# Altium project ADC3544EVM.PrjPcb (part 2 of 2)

## Sheet ADC Inputs.SchDoc: ADC Inputs
size 431 x 279 mm; Date: Not shown in title block; ApprovedBy: Not shown in title block; CheckedBy: Not shown in title block; Author: Not shown in title block; CompanyName: Not shown in title block; Engineer: Not shown in title block; Organization: Not shown in title block; Address1: Not shown in title block; Address2: Not shown in title block; Address3: Not shown in title block; Address4: Not shown in title block; DocumentNumber: 1; Revision: Use project parameter SCH_Rev; SheetNumber: 9; SheetTotal: 15; PageSetup: Record=PageOptions¦CenterHorizontal=True¦CenterVertical=True¦PrintScale=1.00¦XCorrection=1.00¦YCorrection=1.00¦PrintKind=0¦BorderSize=5000000¦LeftOffset=0¦BottomOffset=0¦Orientation=2¦PaperLength=1000¦PaperWidth=1000¦Scale=100¦PaperSource=15¦PrintQuality=600¦MediaType=1¦DitherType=10¦PaperKind=Letter¦PrintScaleMode=1
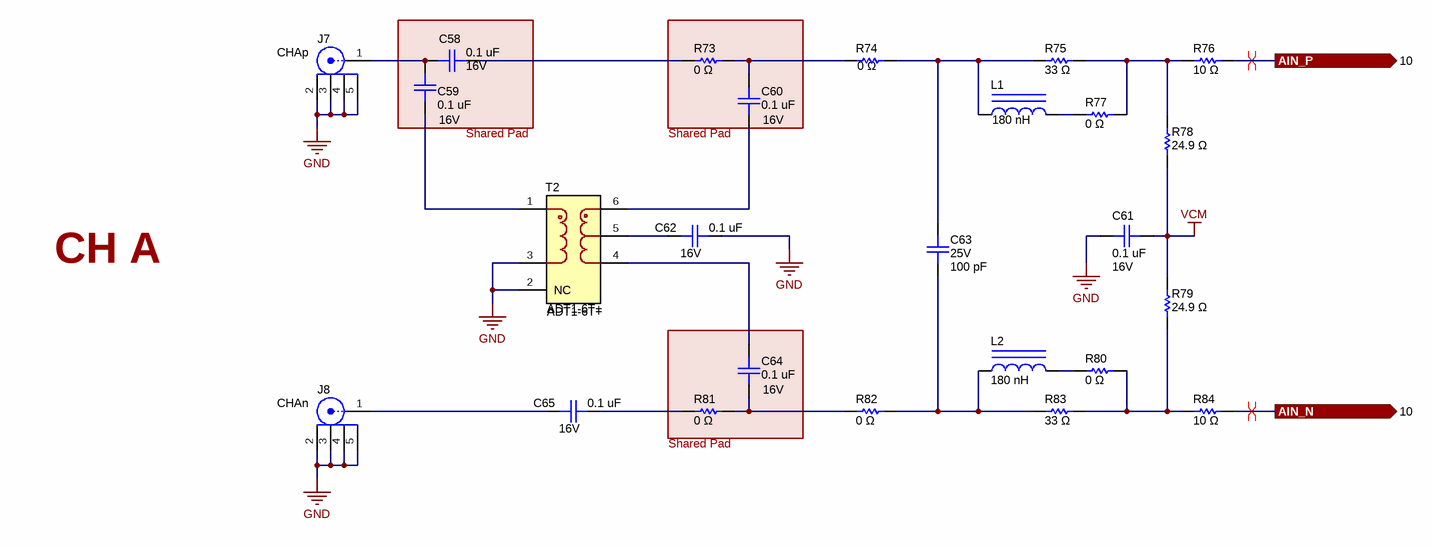
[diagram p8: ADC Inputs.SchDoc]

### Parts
(Parts that share a designator on the sheet are numbered #1, #2 ... from top to bottom, then left to right.)
?#4  Shared Pad  (graphical)
?#5  Shared Pad  (graphical)
?#6  Shared Pad  (graphical)
C58  value 0.1 uF  Voltage - Rated: 16V  [0201_cap]  (hidden comment: GRM033Z71C104ME14D)
C59  value 0.1 uF  Voltage - Rated: 16V  [0201_cap]  (hidden comment: GRM033Z71C104ME14D)
C60  value 0.1 uF  Voltage - Rated: 16V  [0201_cap]  (hidden comment: GRM033Z71C104ME14D)
C61  value 0.1 uF  Voltage - Rated: 16V  [0201_cap]  (hidden comment: GRM033Z71C104ME14D)
C62  value 0.1 uF  Voltage - Rated: 16V  [0201_cap]  (hidden comment: GRM033Z71C104ME14D)
C63  value 100 pF  Voltage - Rated: 25V  [0201_cap]  (hidden comment: CGA1A2X7R1E101M030BA)
C64  value 0.1 uF  Voltage - Rated: 16V  [0201_cap]  (hidden comment: GRM033Z71C104ME14D)
C65  value 0.1 uF  Voltage - Rated: 16V  [0201_cap]  (hidden comment: GRM033Z71C104ME14D)
J7  Text1: CHAp  [FP-132134-15_CONN_SMA_JACK-MFG]  (hidden comment: 132134-15)
J8  Text1: CHAn  [FP-132134-15_CONN_SMA_JACK-MFG]  (hidden comment: 132134-15)
L1  180 nH  [IND_LQG15H]
L2  180 nH  [IND_LQG15H]
R73  value 0 Ω  [0201]  (hidden comment: ERJ-1GN0R00C)
R74  value 0 Ω  [0201]  (hidden comment: ERJ-1GN0R00C)
R75  value 33 Ω  [0201]  (hidden comment: ERJ-1GNF33R0C)
R76  value 10 Ω  [0201]  (hidden comment: ERJ-1GNF10R0C)
R77  value 0 Ω  [0201]  (hidden comment: ERJ-1GN0R00C)
R78  value 24.9 Ω  [0201]  (hidden comment: ERJ-1GNF24R9C)
R79  value 24.9 Ω  [0201]  (hidden comment: ERJ-1GNF24R9C)
R80  value 0 Ω  [0201]  (hidden comment: ERJ-1GN0R00C)
R81  value 0 Ω  [0201]  (hidden comment: ERJ-1GN0R00C)
R82  value 0 Ω  [0201]  (hidden comment: ERJ-1GN0R00C)
R83  value 33 Ω  [0201]  (hidden comment: ERJ-1GNF33R0C)
R84  value 10 Ω  [0201]  (hidden comment: ERJ-1GNF10R0C)
T2  ADT1-6T+  [CD637]

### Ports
AIN_N (out, see 10), AIN_P (out, see 10)

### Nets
GND: C61.1 C62.2 J7.2 J7.3 J7.4 J7.5 J8.2 J8.3 J8.4 J8.5 T2.2(NC) T2.3
VCM: C61.2 R78.1 R79.2
AIN_N: R84.2 ; port AIN_N
AIN_P: R76.2 ; port AIN_P
NetC58_1: C58.1 C59.1 J7.1
NetC58_2: C58.2 R73.1
NetC59_2: C59.2 T2.1
NetC60_1: C60.1 T2.6
NetC60_2: C60.2 R73.2 R74.1
NetC62_1: C62.1 T2.5
NetC63_1: C63.1 L2.1 R82.2 R83.1
NetC63_2: C63.2 L1.1 R74.2 R75.1
NetC64_1: C64.1 R81.2 R82.1
NetC64_2: C64.2 T2.4
NetC65_1: C65.1 J8.1
NetC65_2: C65.2 R81.1
NetL1_2: L1.2 R77.1
NetL2_2: L2.2 R80.1
NetR75_2: R75.2 R76.1 R77.2 R78.2
NetR79_1: R79.1 R80.2 R83.2 R84.1

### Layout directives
differential pair: AIN_N, AIN_P

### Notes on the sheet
- CH A

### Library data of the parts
?#4-?#6 = Swizzle: Schematic notation to show that the pads of two components should be overlapped
C58-C62 C64 C65 = capcc09270: CAP CER 0.1UF 16V X7R 0201; Manufacturer: Murata Electronics; CompType: Capacitor Ceramic; Tolerance: ±20%; SizeX_mm: 0.6; SizeY_mm: 0.3; SizeZ_mm: 0.33
C63 = capcc06388: CAP CER 100PF 25V X7R 0201; Manufacturer: TDK Corporation; CompType: Capacitor Ceramic; Tolerance: ±20%; SizeX_mm: 0.6; SizeY_mm: 0.3; SizeZ_mm: 0.33
J7 J8 = 132134-15: SMA Connector Jack, Female Socket 50Ohm Surface Mount, Through Hole Solder; Manufacturer: Amphenol RF; UniqueID: cmp00028; CompType: RF Connector
L1 L2 = LQG15HSR18J02D: Inductor, Multilayer, Air Core, 180 nH, 0.14 A, 3.38 ohm, SMD; Manufacturer: MuRata; Isat: 0.14A @ % inductance drop; Irms: 0.14A @ C rise; Green_Lifecycle: Active; SizeAreaWB_mm2: 3; DCR_ohm: 3.38; Green_REACh: Passed; Value: 180nH; Imax_A: 140mA; SizeZ_mm: 0.55; SizeX_mm: 1; SizeY_mm: 0.5; Value2: 0.14A; AEC Category: Q200
R73 R74 R77 R80-R82 = RSMD020101699: RES SMD 0 OHM JUMPER 1/20W 0201; Manufacturer: Panasonic Electronic Components; CompType: Resistor SMD; Power (Watts): 0.05W, 1/20W
R75 R83 = RSMD020100013: RES SMD 33 OHM 1% 1/20W 0201; Manufacturer: Panasonic Electronic Components; CompType: Resistor SMD; Power (Watts): 0.05W, 1/20W; Temperature Coefficient: ±200ppm/°C
R76 R84 = RSMD020100179: RES SMD 10 OHM 1% 1/20W 0201; Manufacturer: Panasonic Electronic Components; CompType: Resistor SMD; Power (Watts): 0.05W, 1/20W; Temperature Coefficient: ±200ppm/°C
R78 R79 = RSMD020100010: RES SMD 24.9 OHM 1% 1/20W 0201; Manufacturer: Panasonic Electronic Components; CompType: Resistor SMD; Power (Watts): 0.05W, 1/20W; Temperature Coefficient: ±200ppm/°C
T2 = ADT1-6T+: Transformer 50Ω/0.03 to 125 MHz; Manufacturer: Mini-Circuits; Rsec1_ohm: 50; Symbol Name: SYM-ADT1-6T+; Ns1toNp: 1:1; SizeZ_mm: .206inch; AEC Qualified: No

## Sheet DUT IO.SchDoc: ADC IO
size 431 x 279 mm; Date: Not shown in title block; ApprovedBy: Not shown in title block; CheckedBy: Not shown in title block; Author: Not shown in title block; CompanyName: Not shown in title block; Engineer: Not shown in title block; Organization: Not shown in title block; Address1: Not shown in title block; Address2: Not shown in title block; Address3: Not shown in title block; Address4: Not shown in title block; DocumentNumber: 1; Revision: Use project parameter SCH_Rev; SheetNumber: 10; SheetTotal: 15; PageSetup: Record=PageOptions¦CenterHorizontal=True¦CenterVertical=True¦PrintScale=1.00¦XCorrection=1.00¦YCorrection=1.00¦PrintKind=0¦BorderSize=5000000¦LeftOffset=0¦BottomOffset=0¦Orientation=2¦PaperLength=1000¦PaperWidth=1000¦Scale=100¦PaperSource=15¦PrintQuality=600¦MediaType=1¦DitherType=10¦PaperKind=Letter¦PrintScaleMode=1
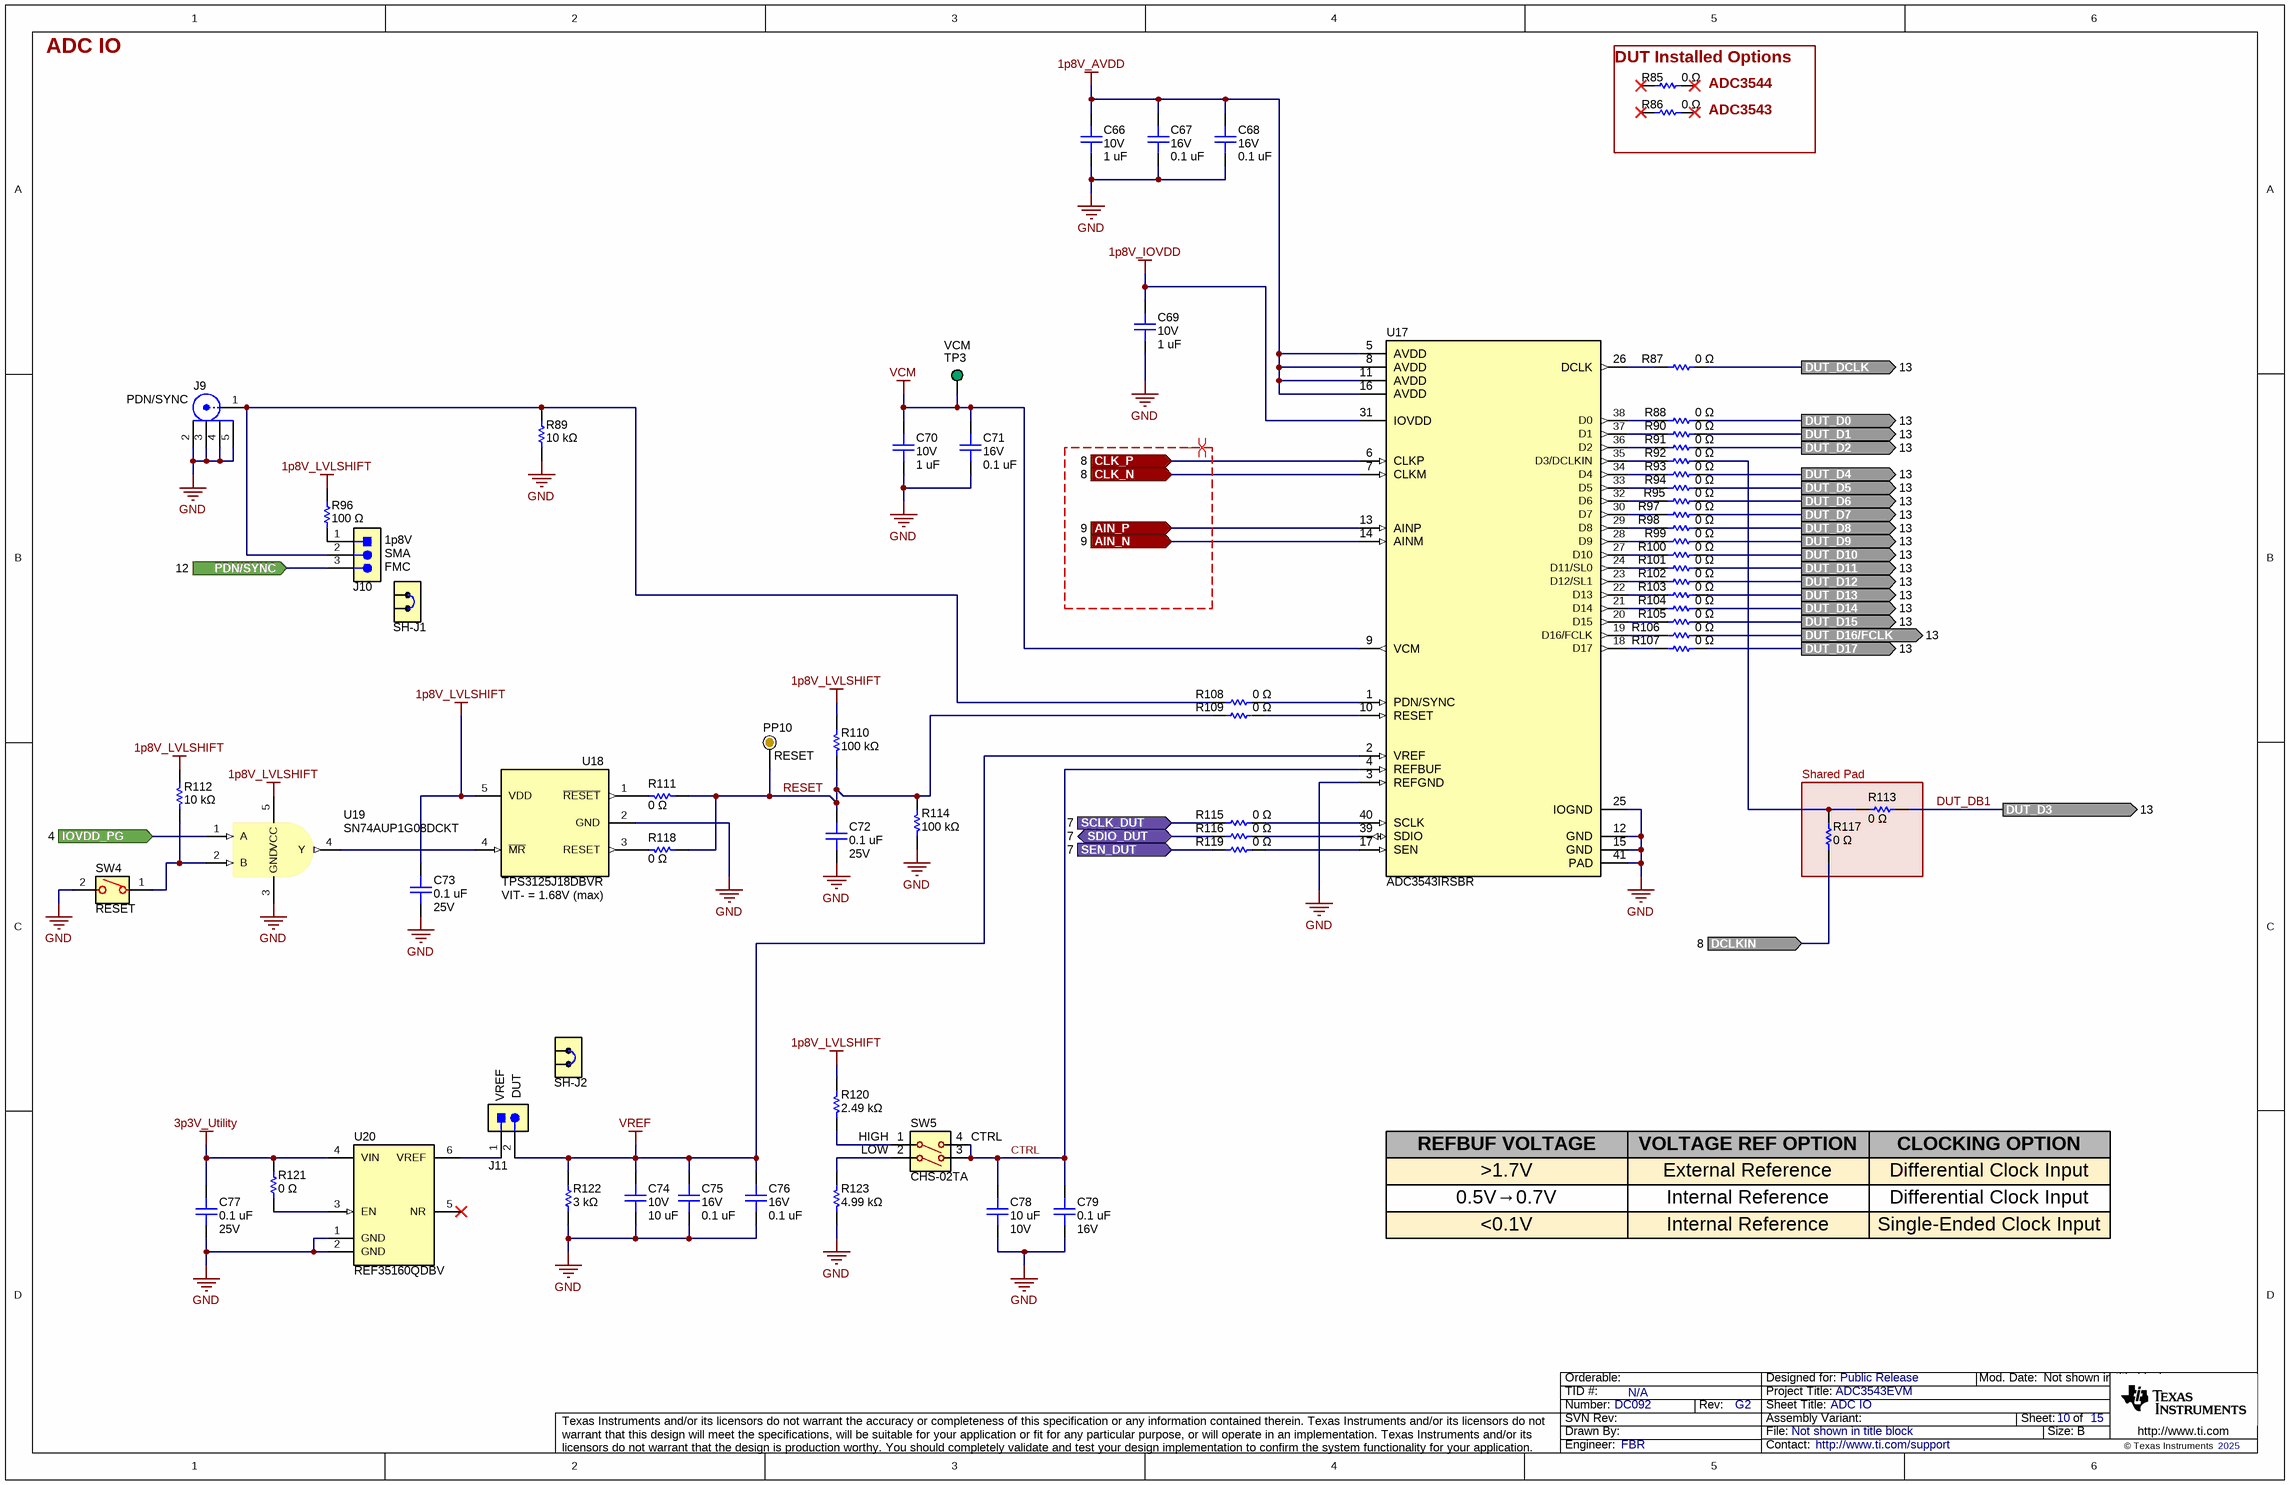
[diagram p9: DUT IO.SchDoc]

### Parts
(Parts that share a designator on the sheet are numbered #1, #2 ... from top to bottom, then left to right.)
?#7  Shared Pad  (graphical)
C66  value 1 uF  Voltage - Rated: 10V  [0201_cap]  (hidden comment: GRM033R61A105ME44D)
C67  value 0.1 uF  Voltage - Rated: 16V  [0201_cap]  (hidden comment: GRM033Z71C104ME14D)
C68  value 0.1 uF  Voltage - Rated: 16V  [0201_cap]  (hidden comment: GRM033Z71C104ME14D)
C69  value 1 uF  Voltage - Rated: 10V  [0201_cap]  (hidden comment: GRM033R61A105ME44D)
C70  value 1 uF  Voltage - Rated: 10V  [0201_cap]  (hidden comment: GRM033R61A105ME44D)
C71  value 0.1 uF  Voltage - Rated: 16V  [0201_cap]  (hidden comment: GRM033Z71C104ME14D)
C72  value 0.1 uF  Voltage - Rated: 25V  [0402L_cap]  (hidden comment: GRT155R71E104KE01J)
C73  value 0.1 uF  Voltage - Rated: 25V  [0402L_cap]  (hidden comment: GRT155R71E104KE01J)
C74  value 10 uF  Voltage - Rated: 10V  [0402L_cap]  (hidden comment: 0402ZD106MAT2A)
C75  value 0.1 uF  Voltage - Rated: 16V  [0201_cap]  (hidden comment: GRM033Z71C104ME14D)
C76  value 0.1 uF  Voltage - Rated: 16V  [0201_cap]  (hidden comment: GRM033Z71C104ME14D)
C77  value 0.1 uF  Voltage - Rated: 25V  [0402L_cap]  (hidden comment: GRT155R71E104KE01J)
C78  value 10 uF  Voltage - Rated: 10V  [0402L_cap]  (hidden comment: 0402ZD106MAT2A)
C79  value 0.1 uF  Voltage - Rated: 16V  [0201_cap]  (hidden comment: GRM033Z71C104ME14D)
J9  Text1: PDN/SYNC  [FP-132134-15_CONN_SMA_JACK-MFG]  (hidden comment: 132134-15)
J10  Text3: FMC  Text2: SMA  Text1: 1p8V  [PBC03SAAN]  (hidden comment: TSW-103-14-L-S)
J11  Text2: DUT  Text1: VREF  [HDR_2x1_TH_VT_50mil]  (hidden comment: GRPB021VWVN-RC)
PP10  Text1: RESET  [ProbePoint_TH_40mil]  (hidden comment: Probe Point)  (no BOM)
R85  value 0 Ω  [0805L]  (hidden comment: ERJ-6GEY0R00V)
R86  value 0 Ω  [0805L]  (hidden comment: ERJ-6GEY0R00V)
R87  value 0 Ω  [0201]  (hidden comment: ERJ-1GN0R00C)
R88  value 0 Ω  [0201]  (hidden comment: ERJ-1GN0R00C)
R89  value 10 kΩ  [0402L]  (hidden comment: ERA-2AEB103X)
R90  value 0 Ω  [0201]  (hidden comment: ERJ-1GN0R00C)
R91  value 0 Ω  [0201]  (hidden comment: ERJ-1GN0R00C)
R92  value 0 Ω  [0201]  (hidden comment: ERJ-1GN0R00C)
R93  value 0 Ω  [0201]  (hidden comment: ERJ-1GN0R00C)
R94  value 0 Ω  [0201]  (hidden comment: ERJ-1GN0R00C)
R95  value 0 Ω  [0201]  (hidden comment: ERJ-1GN0R00C)
R96  value 100 Ω  [0402L]  (hidden comment: ERJ-2GEJ101X)
R97  value 0 Ω  [0201]  (hidden comment: ERJ-1GN0R00C)
R98  value 0 Ω  [0201]  (hidden comment: ERJ-1GN0R00C)
R99  value 0 Ω  [0201]  (hidden comment: ERJ-1GN0R00C)
R100  value 0 Ω  [0201]  (hidden comment: ERJ-1GN0R00C)
R101  value 0 Ω  [0201]  (hidden comment: ERJ-1GN0R00C)
R102  value 0 Ω  [0201]  (hidden comment: ERJ-1GN0R00C)
R103  value 0 Ω  [0201]  (hidden comment: ERJ-1GN0R00C)
R104  value 0 Ω  [0201]  (hidden comment: ERJ-1GN0R00C)
R105  value 0 Ω  [0201]  (hidden comment: ERJ-1GN0R00C)
R106  value 0 Ω  [0201]  (hidden comment: ERJ-1GN0R00C)
R107  value 0 Ω  [0201]  (hidden comment: ERJ-1GN0R00C)
R108  value 0 Ω  [0201]  (hidden comment: ERJ-1GN0R00C)
R109  value 0 Ω  [0201]  (hidden comment: ERJ-1GN0R00C)
R110  value 100 kΩ  [0402L]  (hidden comment: ERJ-2GEJ104X)
R111  value 0 Ω  [0402L]  (hidden comment: ERJ-U020R00X)
R112  value 10 kΩ  [0402L]  (hidden comment: ERA-2AEB103X)
R113  value 0 Ω  [0201]  (hidden comment: ERJ-1GN0R00C)
R114  value 100 kΩ  [0402L]  (hidden comment: ERJ-2GEJ104X)
R115  value 0 Ω  [0201]  (hidden comment: ERJ-1GN0R00C)
R116  value 0 Ω  [0201]  (hidden comment: ERJ-1GN0R00C)
R117  value 0 Ω  [0201]  (hidden comment: ERJ-1GN0R00C)
R118  value 0 Ω  [0402L]  (hidden comment: ERJ-U020R00X)
R119  value 0 Ω  [0201]  (hidden comment: ERJ-1GN0R00C)
R120  value 2.49 kΩ  [0201]  (hidden comment: ERJ-1GNF2491C)
R121  value 0 Ω  [0201]  (hidden comment: ERJ-1GN0R00C)
R122  value 3 kΩ  [0201]  (hidden comment: ERJ-1GNF3001C)
R123  value 4.99 kΩ  [0201]  (hidden comment: ERJ-1GNF4991C)
SH-J1  SPC02SYAN  [SPC02SYAN]  (value not drawn)
SH-J2  HMSC-G  [HMSC-G]  (value not drawn)
SW4  Text1: RESET  [FSMSM]  (hidden comment: FSMSM)
SW5  CHS-02TA  Text4: CTRL  Text2: LOW  Text1: HIGH  [CHS-02TA]
TP3  Text1: VCM  [KEYSTONE5116]  (hidden comment: 5116)
U17  ADC3543IRSBR  [RSB0040E]
U18  TPS3125J18DBVR  Text1: VIT- = 1.68V (max)  [DBV0005A]
U19  SN74AUP1G08DCKT  [DCK0005A]
U20  REF35160QDBV  [DBV0006A]

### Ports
AIN_N (in, see 9), AIN_P (in, see 9), CLK_N (in, see 8), CLK_P (in, see 8), DCLKIN (in, see 8), DUT_D0 (out, see 13), DUT_D1 (out, see 13), DUT_D2 (out, see 13), DUT_D3 (out, see 13), DUT_D4 (out, see 13), DUT_D5 (out, see 13), DUT_D6 (out, see 13), DUT_D7 (out, see 13), DUT_D8 (out, see 13), DUT_D9 (out, see 13), DUT_D10 (out, see 13), DUT_D11 (out, see 13), DUT_D12 (out, see 13), DUT_D13 (out, see 13), DUT_D14 (out, see 13), DUT_D15 (out, see 13), DUT_D16/FCLK (out, see 13), DUT_D17 (out, see 13), DUT_DCLK (out, see 13), IOVDD_PG (in, see 4), PDN/SYNC (in, see 12), SCLK_DUT (in, see 7), SDIO_DUT (bidir, see 7), SEN_DUT (in, see 7)

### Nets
1p8V_AVDD: C66.2 C67.2 C68.2 U17.5(AVDD) U17.8(AVDD) U17.11(AVDD) U17.16(AVDD)
1p8V_IOVDD: C69.2 U17.31(IOVDD)
1p8V_LVLSHIFT: C73.2 R96.2 R110.2 R112.1 R120.2 U18.5(VDD) U19.5(VCC)
3p3V_Utility: C77.2 R121.2 U20.4(VIN)
GND: C66.1 C67.1 C68.1 C69.1 C70.1 C71.1 C72.1 C73.1 C74.1 C75.1 C76.1 C77.1 C78.1 C79.1 J9.2 J9.3 J9.4 J9.5 R89.1 R114.1 R122.1 R123.1 SW4.2 U17.3(REFGND) U17.12(GND) U17.15(GND) U17.25(IOGND) U17.41(PAD) U18.2(GND) U19.3(GND) U20.1(GND) U20.2(GND)
VCM: C70.2 C71.2 TP3.1 U17.9(VCM)
VREF: C74.2 C75.2 C76.2 J11.2 R122.2 U17.2(VREF)
AIN_N: U17.14(AINM) ; port AIN_N
AIN_P: U17.13(AINP) ; port AIN_P
CLK_N: U17.7(CLKM) ; port CLK_N
CLK_P: U17.6(CLKP) ; port CLK_P
CTRL: C78.2 C79.2 SW5.3(OFF) SW5.4(OFF) U17.4(REFBUF)
DCLKIN: R117.1 ; port DCLKIN
DUT_D0: R88.2 ; port DUT_D0
DUT_D1: R90.2 ; port DUT_D1
DUT_D2: R91.2 ; port DUT_D2
DUT_D4: R93.2 ; port DUT_D4
DUT_D5: R94.2 ; port DUT_D5
DUT_D6: R95.2 ; port DUT_D6
DUT_D7: R97.2 ; port DUT_D7
DUT_D8: R98.2 ; port DUT_D8
DUT_D9: R99.2 ; port DUT_D9
DUT_D10: R100.2 ; port DUT_D10
DUT_D11: R101.2 ; port DUT_D11
DUT_D12: R102.2 ; port DUT_D12
DUT_D13: R103.2 ; port DUT_D13
DUT_D14: R104.2 ; port DUT_D14
DUT_D15: R105.2 ; port DUT_D15
DUT_D16/FCLK: R106.2 ; port DUT_D16/FCLK
DUT_D17: R107.2 ; port DUT_D17
DUT_DB1: R113.1 ; port DUT_D3
DUT_DCLK: R87.2 ; port DUT_DCLK
IOVDD_PG: U19.1(A) ; port IOVDD_PG
PDN/SYNC: J10.3 ; port PDN/SYNC
RESET: C72.2 PP10.1 R109.1 R110.1 R111.1 R114.2 R118.1
SCLK_DUT: R115.1 ; port SCLK_DUT
SDIO_DUT: R116.1 ; port SDIO_DUT
SEN_DUT: R119.1 ; port SEN_DUT
NetJ9_1: J9.1 J10.2 R89.2 R108.1
NetJ10_1: J10.1 R96.1
NetJ11_1: J11.1 U20.6(VREF)
NetR87_1: R87.1 U17.26(DCLK)
NetR88_1: R88.1 U17.38(D0)
NetR90_1: R90.1 U17.37(D1)
NetR91_1: R91.1 U17.36(D2)
NetR92_1: R92.1 U17.35(D3/DCLKIN)
NetR92_2: R92.2 R113.2 R117.2
NetR93_1: R93.1 U17.34(D4)
NetR94_1: R94.1 U17.33(D5)
NetR95_1: R95.1 U17.32(D6)
NetR97_1: R97.1 U17.30(D7)
NetR98_1: R98.1 U17.29(D8)
NetR99_1: R99.1 U17.28(D9)
NetR100_1: R100.1 U17.27(D10)
NetR101_1: R101.1 U17.24(D11/SL0)
NetR102_1: R102.1 U17.23(D12/SL1)
NetR103_1: R103.1 U17.22(D13)
NetR104_1: R104.1 U17.21(D14)
NetR105_1: R105.1 U17.20(D15)
NetR106_1: R106.1 U17.19(D16/FCLK)
NetR107_1: R107.1 U17.18(D17)
NetR108_2: R108.2 U17.1(PDN/SYNC)
NetR109_2: R109.2 U17.10(RESET)
NetR111_2: R111.2 U18.1(~{RESET})
NetR112_2: R112.2 SW4.1 U19.2(B)
NetR115_2: R115.2 U17.40(SCLK)
NetR116_2: R116.2 U17.39(SDIO)
NetR118_2: R118.2 U18.3(RESET)
NetR119_2: R119.2 U17.17(SEN)
NetR120_1: R120.1 SW5.1(ON)
NetR121_1: R121.1 U20.3(EN)
NetR123_2: R123.2 SW5.2(ON)
NetU18_4: U18.4(~{MR}) U19.4(Y)

Not connected (* = marked no-connect by the designer): R85 1* 2*; R86 1* 2*; U20 5(NR)*

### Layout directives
differential pair; net class DiffPairIN: (no net found under the mark)

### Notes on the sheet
- ADC3544
- DUT Installed Options
- ADC3543
- REFBUF VOLTAGE
- VOLTAGE REF OPTION
- CLOCKING OPTION
- >1.7V
- 0.5V→0.7V
- <0.1V
- External Reference
- Internal Reference
- Differential Clock Input
- Single-Ended Clock Input

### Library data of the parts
?#7 = Swizzle: as ?#4-?#6 on sheet ADC Inputs
C66 C69 C70 = capcc09264: CAP CER 1UF 10V X5R 0201; Manufacturer: Murata Electronics; CompType: Capacitor Ceramic; Tolerance: ±20%; SizeX_mm: 0.6; SizeY_mm: 0.3; SizeZ_mm: 0.33
C67 C68 C71 C75 C76 C79 = capcc09270: as C58-C62 on sheet ADC Inputs
C72 C73 C77 = capcc09401: CAP CER 0.1UF 25V X7R 0402; Manufacturer: Murata; CompType: Capacitor Ceramic; Tolerance: ±10%; SizeX_mm: 1; SizeY_mm: 0.5; SizeZ_mm: 0.7
C74 C78 = capcc09406: CAP CER 10UF 10V X5R 0402; Manufacturer: KYOCERA AVX; CompType: Capacitor Ceramic; Tolerance: ±20%; SizeX_mm: 1; SizeY_mm: 0.5; SizeZ_mm: 0.7
J9 = 132134-15: as J7 on sheet ADC Inputs
J10 = TSW-103-14-L-S: Header, 100mil, 3x1, Gold, TH; Manufacturer: Samtec; Alt Manufacturer: Sullins Connector Solutions; UniqueID: cmp00015; Pitch (mm): 2.54
J11 = cmp00298: Header, 50mil, 2x1, Gold, TH; Manufacturer: Sullins Connector Solutions; Pitch (mm): 1.27
PP10 = Probe Point: Probe Point that can be used in lue of a test point; UniqueID: cmp00025
R85 R86 = RSMD080510615: RES SMD 0 OHM JUMPER 1/8W 0805; Manufacturer: Panasonic Electronic Components; CompType: Resistor SMD; Power (Watts): 0.125W, 1/8W; SizeX_mm: 2; SizeY_mm: 1.25; SizeZ_mm: 0.7
R87 R88 R90-R95 R97-R109 R113 R115-R117 R119 R121 = RSMD020101699: as R73 on sheet ADC Inputs
R89 R112 = RSMD040200315: RES SMD 10K OHM 0.1% 1/16W 0402; Manufacturer: Panasonic Electronic Components; CompType: Resistor SMD; Power (Watts): 0.063W, 1/16W; Temperature Coefficient: ±25ppm/°C; SizeX_mm: 1; SizeY_mm: 0.5; SizeZ_mm: 0.4
R96 = RSMD040200370: RES SMD 100 OHM 5% 1/10W 0402; Manufacturer: Panasonic Electronic Components; CompType: Resistor SMD; Power (Watts): 0.1W, 1/10W; Temperature Coefficient: ±200ppm/°C; SizeX_mm: 1; SizeY_mm: 0.5; SizeZ_mm: 0.4
R110 R114 = RSMD040200354: RES SMD 100K OHM 5% 1/10W 0402; Manufacturer: Panasonic Electronic Components; CompType: Resistor SMD; Power (Watts): 0.1W, 1/10W; Temperature Coefficient: ±200ppm/°C; SizeX_mm: 1; SizeY_mm: 0.5; SizeZ_mm: 0.4
R111 R118 = RSMD040200004: RES 0 OHM JUMPER 0402 SMD; Manufacturer: Panasonic Electronic Components; CompType: Resistor SMD; Power (Watts): 0.1W, 1/10W; Temperature Coefficient: -100/ +600ppm/°C; SizeX_mm: 1; SizeY_mm: 0.5; SizeZ_mm: 0.4
R120 = RSMD020100692: RES SMD 2.49K OHM 1% 1/20W 0201; Manufacturer: Panasonic Electronic Components; CompType: Resistor SMD; Power (Watts): 0.05W, 1/20W; Temperature Coefficient: ±200ppm/°C
R122 = RSMD020100769: RES SMD 3K OHM 1% 1/20W 0201; Manufacturer: Panasonic Electronic Components; CompType: Resistor SMD; Power (Watts): 0.05W, 1/20W; Temperature Coefficient: ±200ppm/°C
R123 = RSMD020100641: RES SMD 4.99K OHM 1% 1/20W 0201; Manufacturer: Panasonic Electronic Components; CompType: Resistor SMD; Power (Watts): 0.05W, 1/20W; Temperature Coefficient: ±200ppm/°C
SH-J1 = cmp00299: 2 (1 x 2) Position Shunt Connector Black Closed Top 0.050" (1.27mm) Gold; Manufacturer: Adam Tech; PartNumber: HMSC-G; Value: 1x2; Note: You can "mate" this to a header by matching the designator.  i.e. use SH-J3 for header J3; Pitch (mm): 1.27
SH-J2 = HMSC-G: 2 (1 x 2) Position Shunt Connector Black Closed Top 0.050" (1.27mm) Gold; Manufacturer: Adam Tech; Value: 1x2; Key: SPC02SYAN; Note: You can "mate" this to a header by matching the designator.  i.e. use SH-J3 for header J3; Pitch (mm): 1.27
SW4 = cmp00234: SWITCH TACTILE SPST-NO 0.05A 24V; Manufacturer: TE Connectivity; CompType: Push Button
SW5 = CHS-02TA: SWITCH SLIDE DIP SPST 0.1A 6V; Manufacturer: Nidec Components Corporation; CompType: Swtich
TP3 = cmp00057: Test Point, Miniature, Green, TH; Manufacturer: Keystone
U17 = ADC3543IRSB: Single-channel, 14-bit, 65-MSPS, low-noise, ultra-low-power and low-latency ADC; Manufacturer: Texas Instruments; Alternate PartNumber: ADC3543IRSBT
U18 = cmp00229: Push-pull, supply voltage supervisor with manual reset; Manufacturer: Texas Instruments; Alt PartNumber: TPS3125J18DBVT; CompType: Voltage Detector
U19 = cmp00268: SN74AUP1G08 Low-Power Single 2-Input Positive-AND Gate; Manufacturer: Texas Instruments
U20 = cmp00301: Ultra Low-Power, High-Precision Voltage Reference; Manufacturer: Texas Instruments; Pitch (mm): 1.27

## Sheet FMC+ Sections A-E.SchDoc: FMC+ Section Rows A - E
size 431 x 279 mm; Date: Not shown in title block; ApprovedBy: Not shown in title block; CheckedBy: Not shown in title block; Author: Not shown in title block; CompanyName: Not shown in title block; Engineer: Not shown in title block; Organization: Not shown in title block; Address1: Not shown in title block; Address2: Not shown in title block; Address3: Not shown in title block; Address4: Not shown in title block; DocumentNumber: 2; Revision: Use project parameter SCH_Rev; SheetNumber: 11; SheetTotal: 14; PageSetup: Record=PageOptions¦CenterHorizontal=True¦CenterVertical=True¦PrintScale=1.00¦XCorrection=1.00¦YCorrection=1.00¦PrintKind=0¦BorderSize=5000000¦LeftOffset=0¦BottomOffset=0¦Orientation=2¦PaperLength=1000¦PaperWidth=1000¦Scale=100¦PaperSource=15¦PrintQuality=600¦MediaType=1¦DitherType=10¦PaperKind=Letter¦PrintScaleMode=1
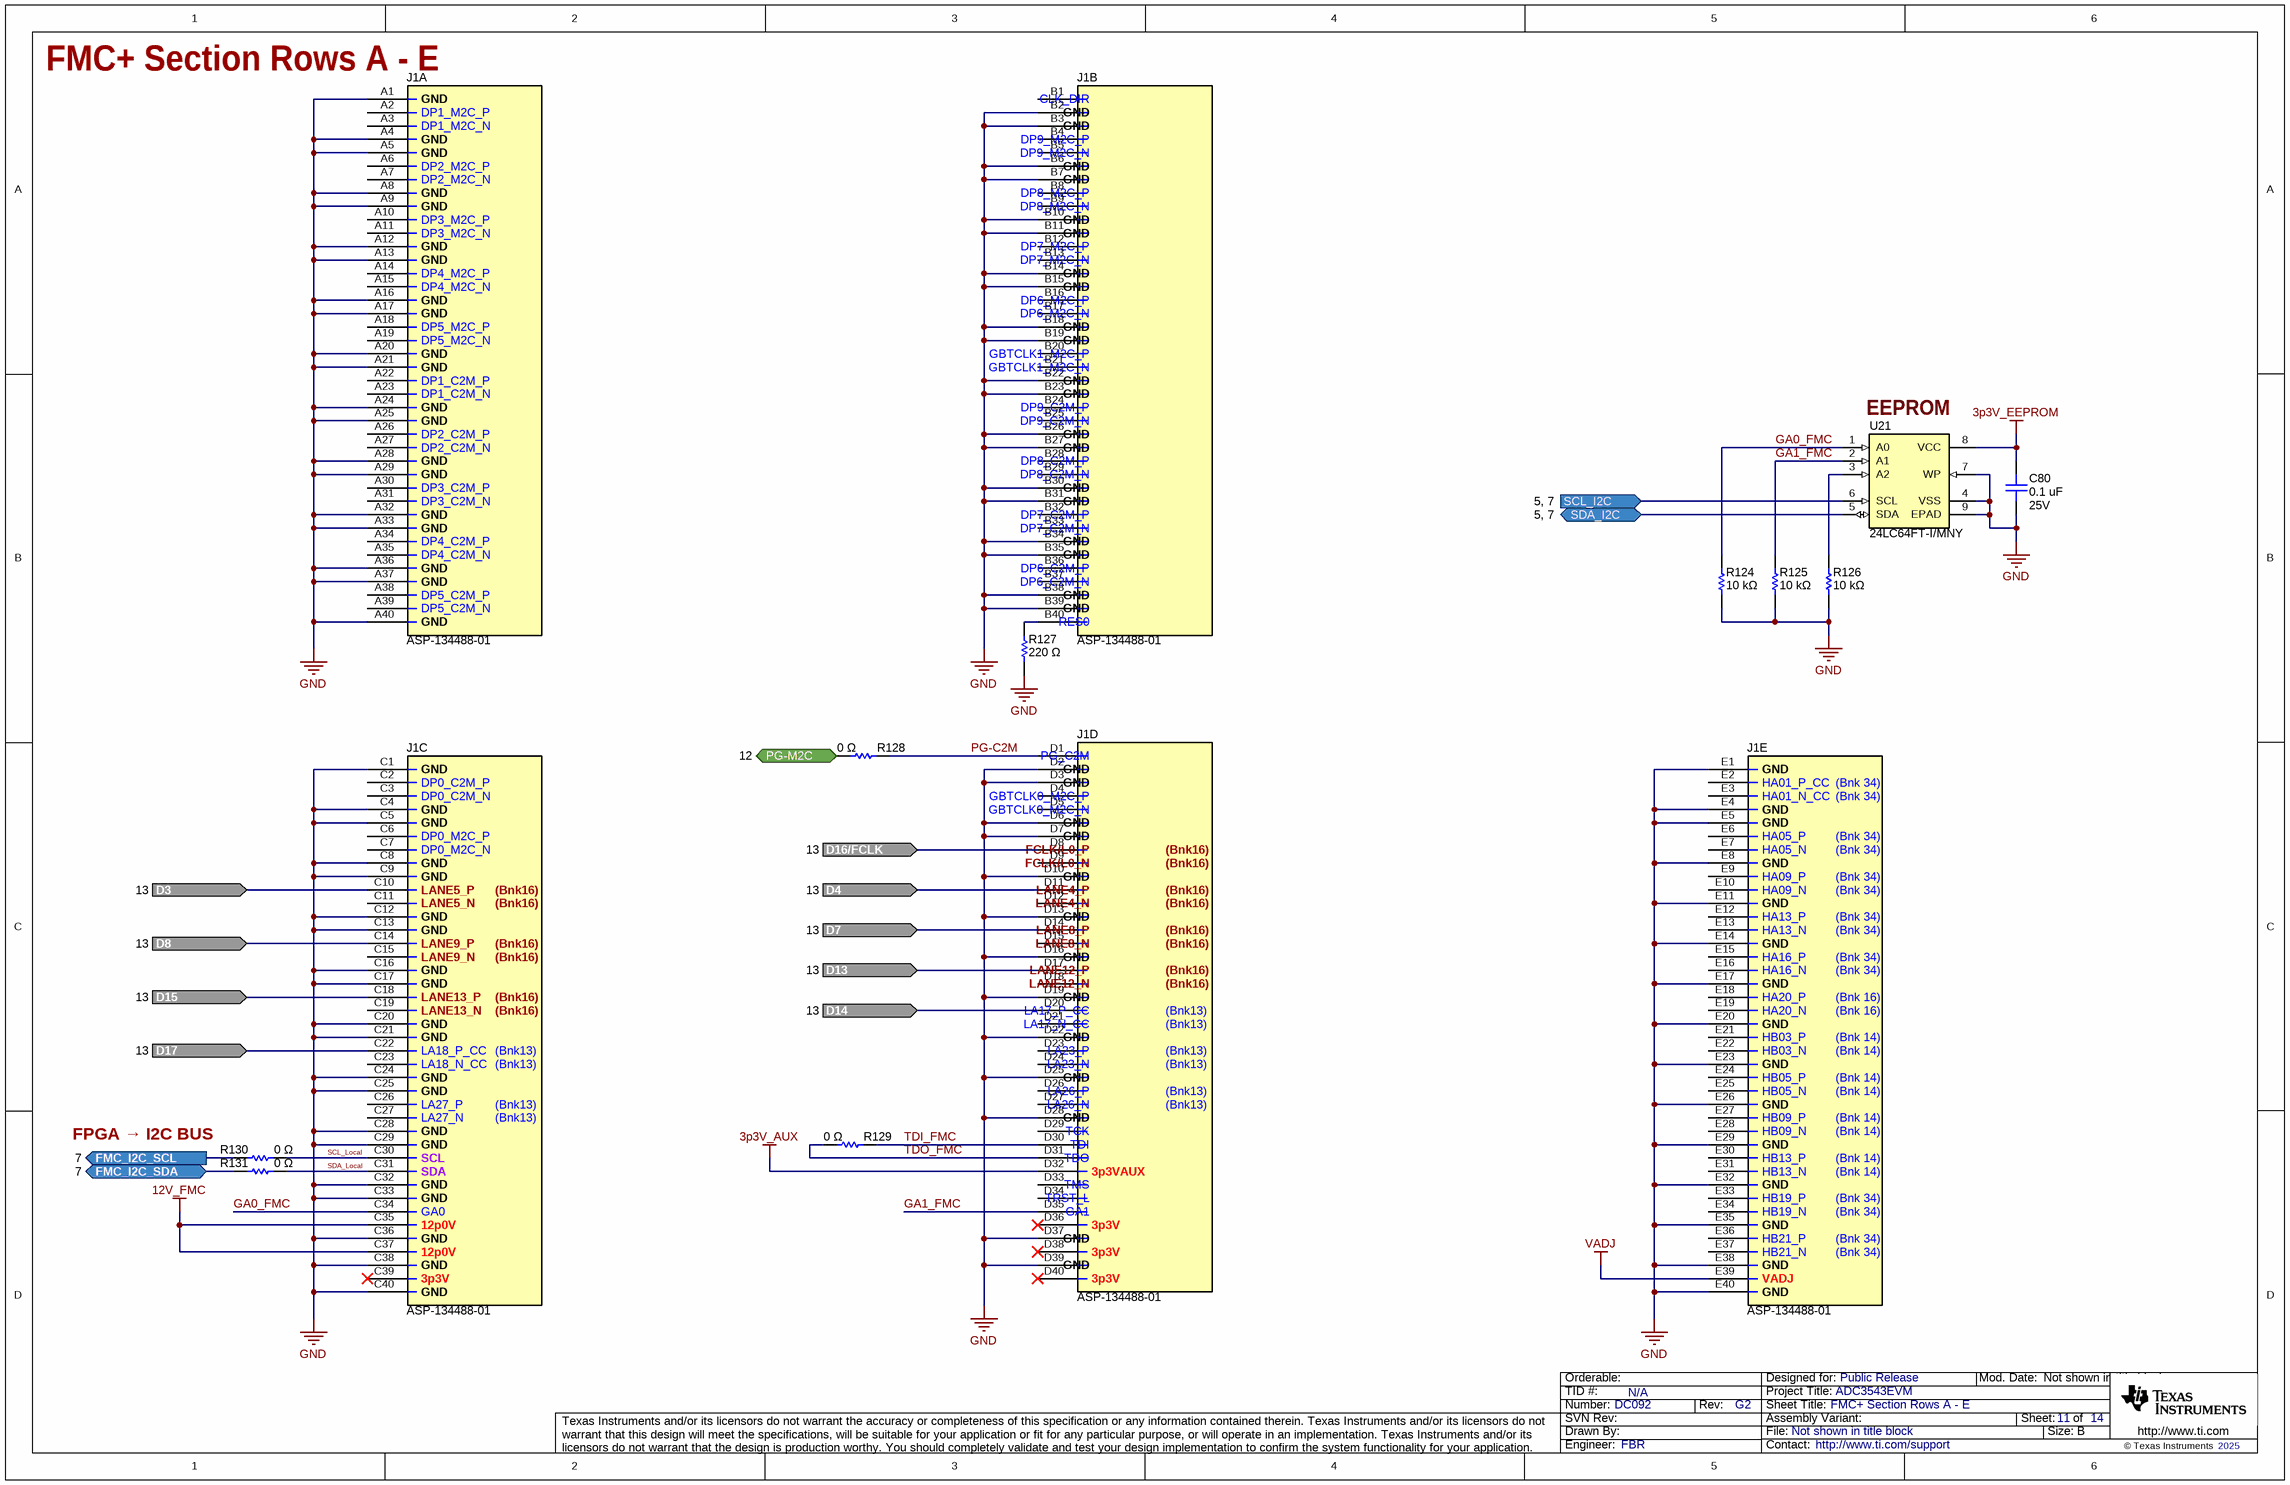
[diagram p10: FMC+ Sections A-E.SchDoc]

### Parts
C80  value 0.1 uF  Voltage - Rated: 25V  [0402L_cap]  (hidden comment: GRT155R71E104KE01J)
J1  ASP-134488-01  [SAMTEC_ASP-134488-01]  (parts A,B,C,D,E of 10)
R124  value 10 kΩ  [0201]  (hidden comment: ERJ-1GNJ103C)
R125  value 10 kΩ  [0201]  (hidden comment: ERJ-1GNJ103C)
R126  value 10 kΩ  [0201]  (hidden comment: ERJ-1GNJ103C)
R127  value 220 Ω  [0201]  (hidden comment: ERJ-1GNF2200C)
R128  value 0 Ω  [0201]  (hidden comment: ERJ-1GN0R00C)
R129  value 0 Ω  [0201]  (hidden comment: ERJ-1GN0R00C)
R130  value 0 Ω  [0201]  (hidden comment: ERJ-1GN0R00C)
R131  value 0 Ω  [0201]  (hidden comment: ERJ-1GN0R00C)
U21  24LC64FT-I/MNY  [TDFN8]

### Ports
D3 (in, see 13), D4 (in, see 13), D7 (in, see 13), D8 (in, see 13), D13 (in, see 13), D14 (in, see 13), D15 (in, see 13), D16/FCLK (in, see 13), D17 (in, see 13), FMC_I2C_SCL (out, see 7), FMC_I2C_SDA (bidir, see 7), PG-M2C (bidir, see 12), SCL_I2C (in, see 5, 7), SDA_I2C (bidir, see 5, 7)

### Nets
3p3V_AUX: J1.D32
3p3V_EEPROM: C80.2 U21.8(VCC)
12V_FMC: J1.C35 J1.C37
GND: C80.1 J1.A1 J1.A4 J1.A5 J1.A8 J1.A9 J1.A12 J1.A13 J1.A16 J1.A17 J1.A20 J1.A21 J1.A24 J1.A25 J1.A28 J1.A29 J1.A32 J1.A33 J1.A36 J1.A37 J1.A40 J1.B2 J1.B3 J1.B6 J1.B7 J1.B10 J1.B11 J1.B14 J1.B15 J1.B18 J1.B19 J1.B22 J1.B23 J1.B26 J1.B27 J1.B30 J1.B31 J1.B34 J1.B35 J1.B38 J1.B39 J1.C1 J1.C4 J1.C5 J1.C8 J1.C9 J1.C12 J1.C13 J1.C16 J1.C17 J1.C20 J1.C21 J1.C24 J1.C25 J1.C28 J1.C29 J1.C32 J1.C33 J1.C36 J1.C38 J1.C40 J1.D2 J1.D3 J1.D6 J1.D7 J1.D10 J1.D13 J1.D16 J1.D19 J1.D22 J1.D25 J1.D28 J1.D37 J1.D39 J1.E1 J1.E4 J1.E5 J1.E8 J1.E11 J1.E14 J1.E17 J1.E20 J1.E23 J1.E26 J1.E29 J1.E32 J1.E35 J1.E38 J1.E40 R124.1 R125.1 R126.1 R127.1 U21.4(VSS) U21.7(WP) U21.9(EPAD)
VADJ: J1.E39
D3: J1.C10 ; port D3
D4: J1.D11 ; port D4
D7: J1.D14 ; port D7
D8: J1.C14 ; port D8
D13: J1.D17 ; port D13
D14: J1.D20 ; port D14
D15: J1.C18 ; port D15
D16/FCLK: J1.D8 ; port D16/FCLK
D17: J1.C22 ; port D17
FMC_I2C_SCL: R130.1 ; port FMC_I2C_SCL
FMC_I2C_SDA: R131.1 ; port FMC_I2C_SDA
GA0_FMC: J1.C34 R124.2 U21.1(A0)
GA1_FMC: J1.D35 R125.2 U21.2(A1)
PG-C2M: J1.D1 R128.2
PG-M2C: R128.1 ; port PG-M2C
SCL_I2C: U21.6(SCL) ; port SCL_I2C
SCL_Local: J1.C30 R130.2
SDA_I2C: U21.5(SDA) ; port SDA_I2C
SDA_Local: J1.C31 R131.2
TDI_FMC: J1.D30 R129.2
TDO_FMC: J1.D31 R129.1
NetJ1_B40: J1.B40 R127.2
NetR126_2: R126.2 U21.3(A2)

Not connected (* = marked no-connect by the designer): J1 A2 A3 A6 A7 A10 A11 A14 A15 A18 A19 A22 A23 A26 A27 A30 A31 A34 A35 A38 A39 B1 B4 B5 B8 B9 B12 B13 B16 B17 B20 B21 B24 B25 B28 B29 B32 B33 B36 B37 C2 C3 C6 C7 C11 C15 C19 C23 C26 C27 C39* D4 D5 D9 D12 D15 D18 D21 D23 D24 D26 D27 D29 D33 D34 D36* D38* D40* E2 E3 E6 E7 E9 E10 E12 E13 E15 E16 E18 E19 E21 E22 E24 E25 E27 E28 E30 E31 E33 E34 E36 E37

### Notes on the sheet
- (near U21) EEPROM
- FPGA → I2C BUS

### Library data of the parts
C80 = capcc09401: as C72 on sheet DUT IO
J1 = ASP-134488-01: FMC, High Density Array, Male / EVM Connector 40x10; Manufacturer: Samtec; UniqueID: cmp00010; Pitch (mm): 1.27
R124-R126 = RSMD020101186: RES SMD 10K OHM 5% 1/20W 0201; Manufacturer: Panasonic Electronic Components; CompType: Resistor SMD; Power (Watts): 0.05W, 1/20W; Temperature Coefficient: ±200ppm/°C
R127 = RSMD020100147: RES SMD 220 OHM 1% 1/20W 0201; Manufacturer: Panasonic Electronic Components; CompType: Resistor SMD; Power (Watts): 0.05W, 1/20W; Temperature Coefficient: ±200ppm/°C
R128-R131 = RSMD020101699: as R73 on sheet ADC Inputs
U21 = cmp00154: EEPROM 64K 8KX8 1.8V SER EE IND 1/4AWP RPO; Manufacturer: Microchip

## Sheet FMC+ Sections F-H, J, K.SchDoc: FMC+ Section Rows F - H, J, K
size 431 x 279 mm; Date: Not shown in title block; ApprovedBy: Not shown in title block; CheckedBy: Not shown in title block; Author: Not shown in title block; CompanyName: Not shown in title block; Engineer: Not shown in title block; Organization: Not shown in title block; Address1: Not shown in title block; Address2: Not shown in title block; Address3: Not shown in title block; Address4: Not shown in title block; DocumentNumber: 3; Revision: Use project parameter SCH_Rev; SheetNumber: 12; SheetTotal: 14; PageSetup: Record=PageOptions¦CenterHorizontal=True¦CenterVertical=True¦PrintScale=1.00¦XCorrection=1.00¦YCorrection=1.00¦PrintKind=0¦BorderSize=5000000¦LeftOffset=0¦BottomOffset=0¦Orientation=2¦PaperLength=1000¦PaperWidth=1000¦Scale=100¦PaperSource=15¦PrintQuality=600¦MediaType=1¦DitherType=10¦PaperKind=Letter¦PrintScaleMode=1
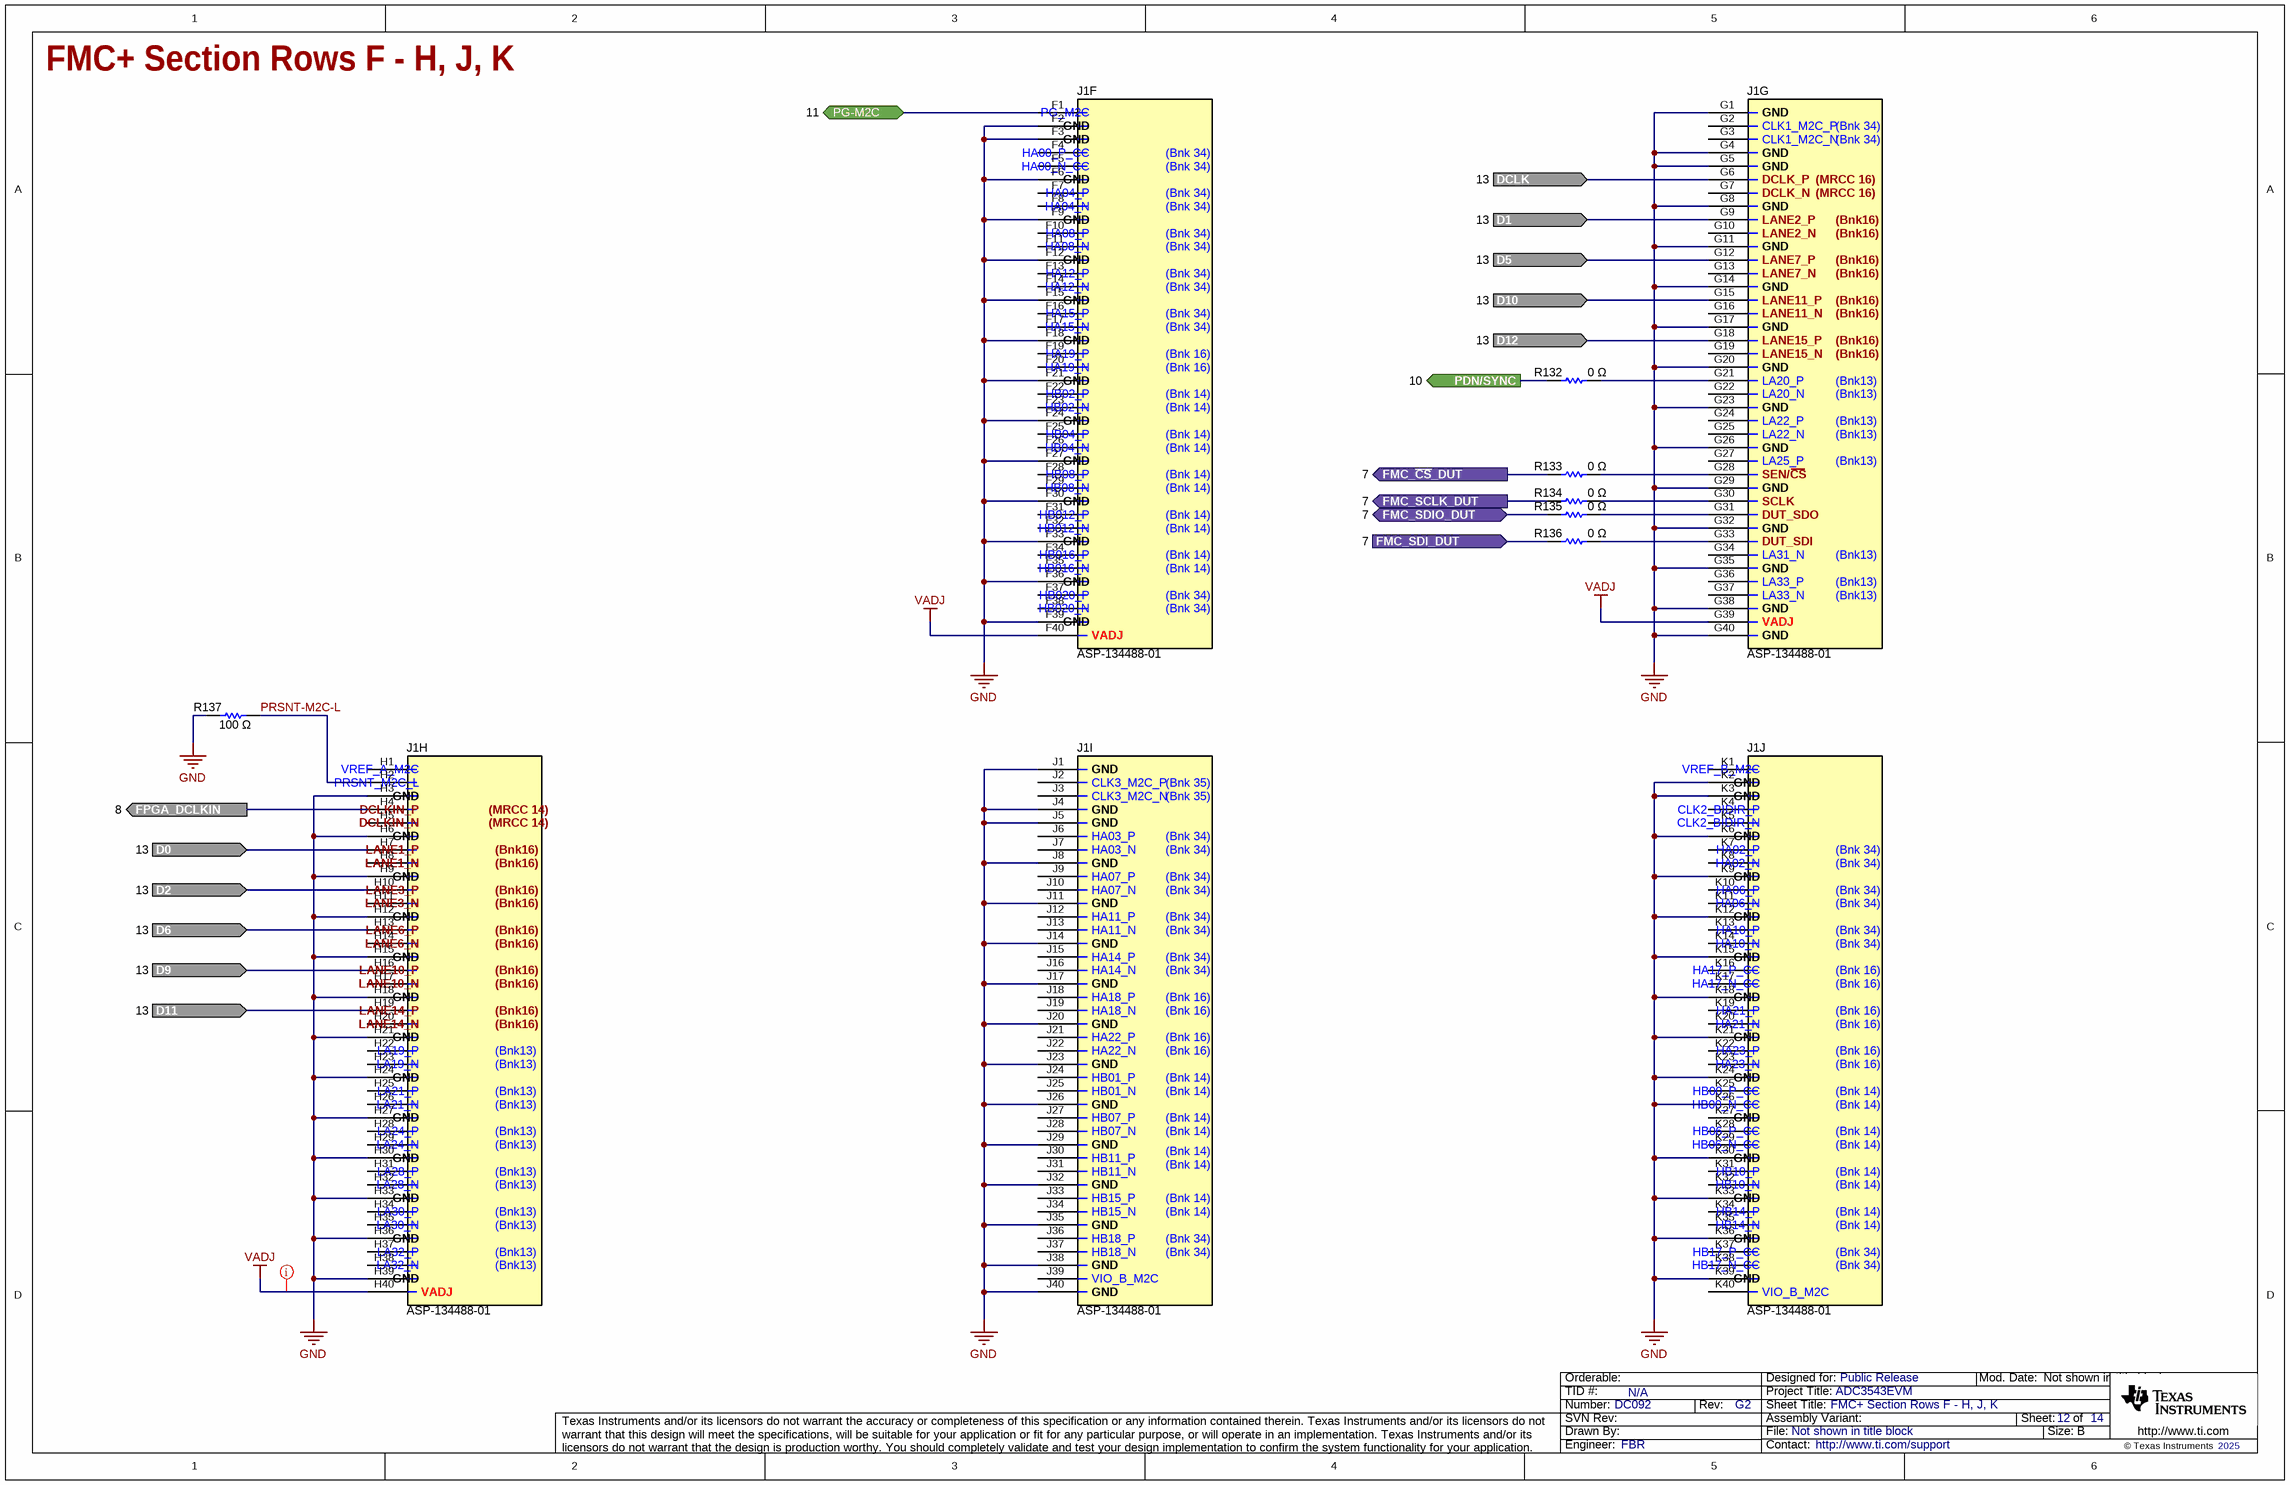
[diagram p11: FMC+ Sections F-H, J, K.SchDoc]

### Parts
J1  ASP-134488-01  [SAMTEC_ASP-134488-01]  (parts F,G,H,I,J of 10)
R132  value 0 Ω  [0201]  (hidden comment: ERJ-1GN0R00C)
R133  value 0 Ω  [0201]  (hidden comment: ERJ-1GN0R00C)
R134  value 0 Ω  [0201]  (hidden comment: ERJ-1GN0R00C)
R135  value 0 Ω  [0201]  (hidden comment: ERJ-1GN0R00C)
R136  value 0 Ω  [0201]  (hidden comment: ERJ-1GN0R00C)
R137  value 100 Ω  [0402L]  (hidden comment: ERJ-2RKF1000X)

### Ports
D0 (in, see 13), D1 (in, see 13), D2 (in, see 13), D5 (in, see 13), D6 (in, see 13), D9 (in, see 13), D10 (in, see 13), D11 (in, see 13), D12 (in, see 13), DCLK (in, see 13), FMC_SCLK_DUT (out, see 7), FMC_SDI_DUT (in, see 7), FMC_SDIO_DUT (bidir, see 7), FMC_~{CS}_DUT (out, see 7), FPGA_DCLKIN (out, see 8), PDN/SYNC (out, see 10), PG-M2C (bidir, see 11)

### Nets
GND: J1.F2 J1.F3 J1.F6 J1.F9 J1.F12 J1.F15 J1.F18 J1.F21 J1.F24 J1.F27 J1.F30 J1.F33 J1.F36 J1.F39 J1.G1 J1.G4 J1.G5 J1.G8 J1.G11 J1.G14 J1.G17 J1.G20 J1.G23 J1.G26 J1.G29 J1.G32 J1.G35 J1.G38 J1.G40 J1.H3 J1.H6 J1.H9 J1.H12 J1.H15 J1.H18 J1.H21 J1.H24 J1.H27 J1.H30 J1.H33 J1.H36 J1.H39 J1.J1 J1.J4 J1.J5 J1.J8 J1.J11 J1.J14 J1.J17 J1.J20 J1.J23 J1.J26 J1.J29 J1.J32 J1.J35 J1.J38 J1.J40 J1.K2 J1.K3 J1.K6 J1.K9 J1.K12 J1.K15 J1.K18 J1.K21 J1.K24 J1.K26 J1.K30 J1.K33 J1.K36 J1.K39 R137.1
VADJ: J1.F40 J1.G39 J1.H40
D0: J1.H7 ; port D0
D1: J1.G9 ; port D1
D2: J1.H10 ; port D2
D5: J1.G12 ; port D5
D6: J1.H13 ; port D6
D9: J1.H16 ; port D9
D10: J1.G15 ; port D10
D11: J1.H19 ; port D11
D12: J1.G18 ; port D12
DCLK: J1.G6 ; port DCLK
FMC_~{CS}_DUT_LVLS: R133.1 ; port FMC_~{CS}_DUT
FMC_SCLK_DUT_LVLS: R134.1 ; port FMC_SCLK_DUT
FMC_SDI_DUT: R136.1 ; port FMC_SDI_DUT
FMC_SDO_DUT_LVLS: R135.1 ; port FMC_SDIO_DUT
FPGA_DCLKIN: J1.H4 ; port FPGA_DCLKIN
PDN/SYNC: R132.1 ; port PDN/SYNC
PG-M2C: J1.F1 ; port PG-M2C
PRSNT-M2C-L: J1.H2 R137.2
NetJ1_G21: J1.G21 R132.2
NetJ1_G28: J1.G28 R133.2
NetJ1_G30: J1.G30 R134.2
NetJ1_G31: J1.G31 R135.2
NetJ1_G33: J1.G33 R136.2

Not connected (* = marked no-connect by the designer): J1 F4 F5 F7 F8 F10 F11 F13 F14 F16 F17 F19 F20 F22 F23 F25 F26 F28 F29 F31 F32 F34 F35 F37 F38 G2 G3 G7 G10 G13 G16 G19 G22 G24 G25 G27 G34 G36 G37 H1 H5 H8 H11 H14 H17 H20 H22 H23 H25 H26 H28 H29 H31 H32 H34 H35 H37 H38 J2 J3 J6 J7 J9 J10 J12 J13 J15 J16 J18 J19 J21 J22 J24 J25 J27 J28 J30 J31 J33 J34 J36 J37 J39 K1 K4 K5 K7 K8 K10 K11 K13 K14 K16 K17 K19 K20 K22 K23 K25 K27 K28 K29 K31 K32 K34 K35 K37 K38 K40

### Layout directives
net class Power; net class FMCPwr: VADJ

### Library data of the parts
J1 = ASP-134488-01: as J1 on sheet FMC+ Sections A-E
R132-R136 = RSMD020101699: as R73 on sheet ADC Inputs
R137 = RSMD040200375: RES SMD 100 OHM 1% 1/10W 0402; Manufacturer: Panasonic Electronic Components; CompType: Resistor SMD; Power (Watts): 0.1W, 1/10W; Temperature Coefficient: ±100ppm/°C; SizeX_mm: 1; SizeY_mm: 0.5; SizeZ_mm: 0.4

## Sheet Ouptut Buffer.SchDoc: Output Buffer
size 431 x 279 mm; Date: Not shown in title block; ApprovedBy: Not shown in title block; CheckedBy: Not shown in title block; Author: Not shown in title block; CompanyName: Not shown in title block; Engineer: Not shown in title block; Organization: Not shown in title block; Address1: Not shown in title block; Address2: Not shown in title block; Address3: Not shown in title block; Address4: Not shown in title block; DocumentNumber: 1; Revision: Use project parameter SCH_Rev; SheetNumber: 13; SheetTotal: 15; PageSetup: Record=PageOptions¦CenterHorizontal=True¦CenterVertical=True¦PrintScale=1.00¦XCorrection=1.00¦YCorrection=1.00¦PrintKind=0¦BorderSize=5000000¦LeftOffset=0¦BottomOffset=0¦Orientation=2¦PaperLength=1000¦PaperWidth=1000¦Scale=100¦PaperSource=15¦PrintQuality=600¦MediaType=1¦DitherType=10¦PaperKind=Letter¦PrintScaleMode=1
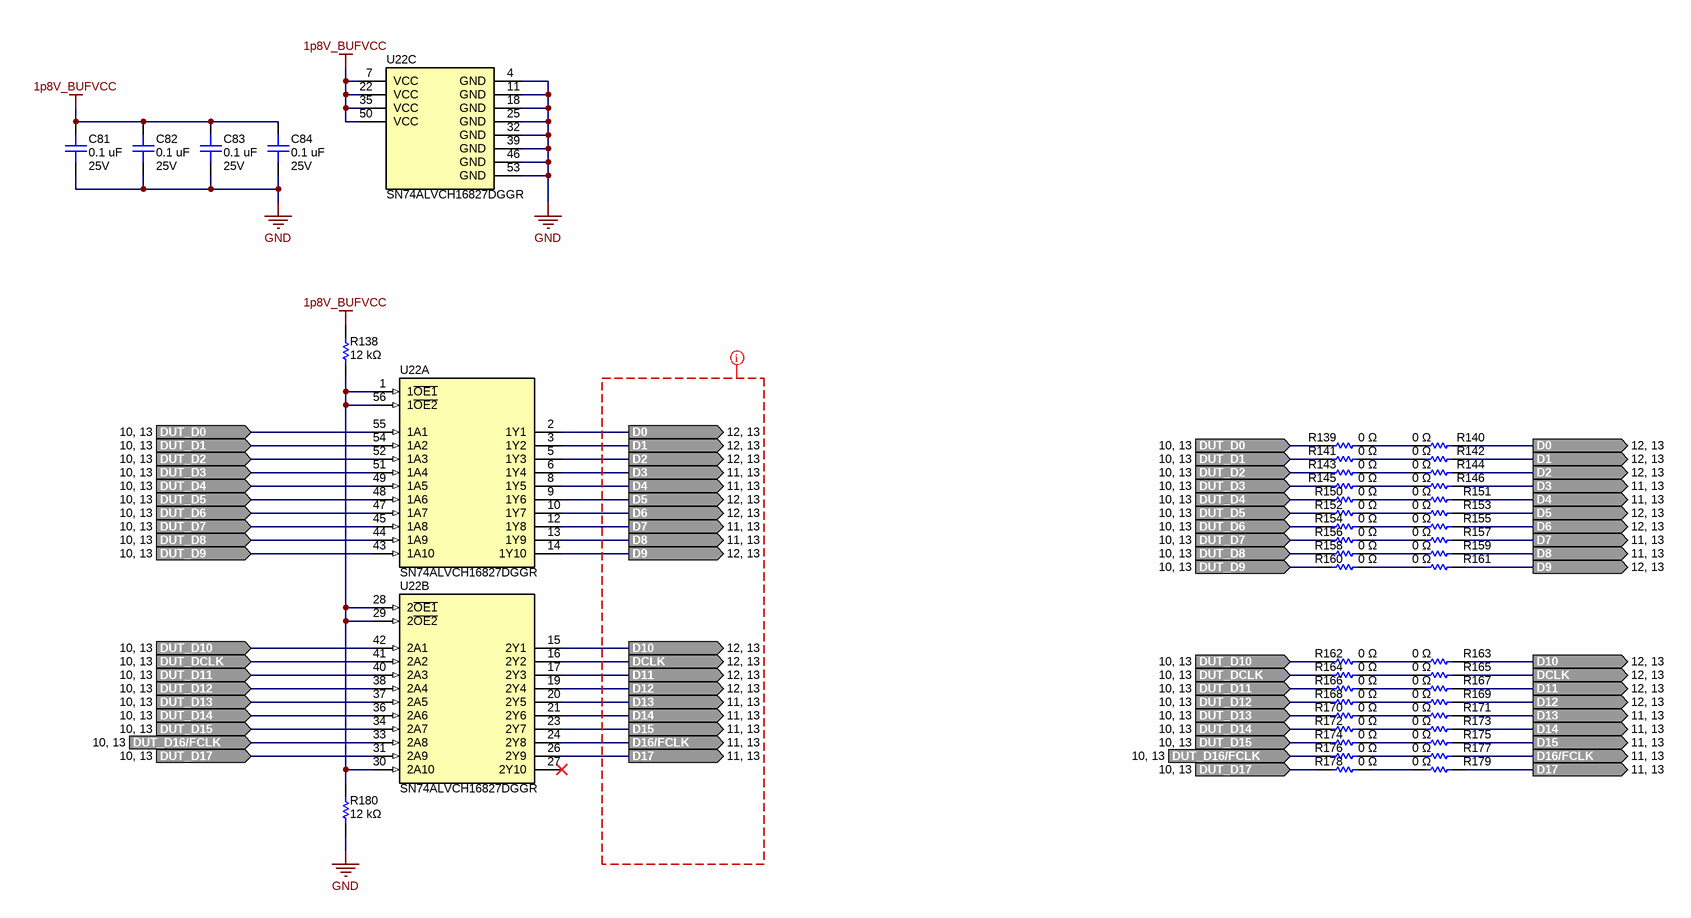
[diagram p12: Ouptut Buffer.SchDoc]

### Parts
C81  value 0.1 uF  Voltage - Rated: 25V  [0402L_cap]  (hidden comment: GRT155R71E104KE01J)
C82  value 0.1 uF  Voltage - Rated: 25V  [0402L_cap]  (hidden comment: GRT155R71E104KE01J)
C83  value 0.1 uF  Voltage - Rated: 25V  [0402L_cap]  (hidden comment: GRT155R71E104KE01J)
C84  value 0.1 uF  Voltage - Rated: 25V  [0402L_cap]  (hidden comment: GRT155R71E104KE01J)
R138  value 12 kΩ  [0201]  (hidden comment: ERJ-1GNJ123C)
R139  value 0 Ω  [0201]  (hidden comment: ERJ-1GN0R00C)
R140  value 0 Ω  [0201]  (hidden comment: ERJ-1GN0R00C)
R141  value 0 Ω  [0201]  (hidden comment: ERJ-1GN0R00C)
R142  value 0 Ω  [0201]  (hidden comment: ERJ-1GN0R00C)
R143  value 0 Ω  [0201]  (hidden comment: ERJ-1GN0R00C)
R144  value 0 Ω  [0201]  (hidden comment: ERJ-1GN0R00C)
R145  value 0 Ω  [0201]  (hidden comment: ERJ-1GN0R00C)
R146  value 0 Ω  [0201]  (hidden comment: ERJ-1GN0R00C)
R150  value 0 Ω  [0201]  (hidden comment: ERJ-1GN0R00C)
R151  value 0 Ω  [0201]  (hidden comment: ERJ-1GN0R00C)
R152  value 0 Ω  [0201]  (hidden comment: ERJ-1GN0R00C)
R153  value 0 Ω  [0201]  (hidden comment: ERJ-1GN0R00C)
R154  value 0 Ω  [0201]  (hidden comment: ERJ-1GN0R00C)
R155  value 0 Ω  [0201]  (hidden comment: ERJ-1GN0R00C)
R156  value 0 Ω  [0201]  (hidden comment: ERJ-1GN0R00C)
R157  value 0 Ω  [0201]  (hidden comment: ERJ-1GN0R00C)
R158  value 0 Ω  [0201]  (hidden comment: ERJ-1GN0R00C)
R159  value 0 Ω  [0201]  (hidden comment: ERJ-1GN0R00C)
R160  value 0 Ω  [0201]  (hidden comment: ERJ-1GN0R00C)
R161  value 0 Ω  [0201]  (hidden comment: ERJ-1GN0R00C)
R162  value 0 Ω  [0201]  (hidden comment: ERJ-1GN0R00C)
R163  value 0 Ω  [0201]  (hidden comment: ERJ-1GN0R00C)
R164  value 0 Ω  [0201]  (hidden comment: ERJ-1GN0R00C)
R165  value 0 Ω  [0201]  (hidden comment: ERJ-1GN0R00C)
R166  value 0 Ω  [0201]  (hidden comment: ERJ-1GN0R00C)
R167  value 0 Ω  [0201]  (hidden comment: ERJ-1GN0R00C)
R168  value 0 Ω  [0201]  (hidden comment: ERJ-1GN0R00C)
R169  value 0 Ω  [0201]  (hidden comment: ERJ-1GN0R00C)
R170  value 0 Ω  [0201]  (hidden comment: ERJ-1GN0R00C)
R171  value 0 Ω  [0201]  (hidden comment: ERJ-1GN0R00C)
R172  value 0 Ω  [0201]  (hidden comment: ERJ-1GN0R00C)
R173  value 0 Ω  [0201]  (hidden comment: ERJ-1GN0R00C)
R174  value 0 Ω  [0201]  (hidden comment: ERJ-1GN0R00C)
R175  value 0 Ω  [0201]  (hidden comment: ERJ-1GN0R00C)
R176  value 0 Ω  [0201]  (hidden comment: ERJ-1GN0R00C)
R177  value 0 Ω  [0201]  (hidden comment: ERJ-1GN0R00C)
R178  value 0 Ω  [0201]  (hidden comment: ERJ-1GN0R00C)
R179  value 0 Ω  [0201]  (hidden comment: ERJ-1GN0R00C)
R180  value 12 kΩ  [0201]  (hidden comment: ERJ-1GNJ123C)
U22  SN74ALVCH16827DGGR  [DGG0056A]  (parts A,B,C of 3)

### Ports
D0 (out, see 12, 13), D1 (out, see 12, 13), D2 (out, see 12, 13), D3 (out, see 11, 13), D4 (out, see 11, 13), D5 (out, see 12, 13), D6 (out, see 12, 13), D7 (out, see 11, 13), D8 (out, see 11, 13), D9 (out, see 12, 13), D10 (out, see 12, 13), D11 (out, see 12, 13), D12 (out, see 12, 13), D13 (out, see 11, 13), D14 (out, see 11, 13), D15 (out, see 11, 13), D16/FCLK (out, see 11, 13), D17 (out, see 11, 13), DCLK (out, see 12, 13), DUT_D0 (in, see 10, 13), DUT_D1 (in, see 10, 13), DUT_D2 (in, see 10, 13), DUT_D3 (in, see 10, 13), DUT_D4 (in, see 10, 13), DUT_D5 (in, see 10, 13), DUT_D6 (in, see 10, 13), DUT_D7 (in, see 10, 13), DUT_D8 (in, see 10, 13), DUT_D9 (in, see 10, 13), DUT_D10 (in, see 10, 13), DUT_D11 (in, see 10, 13), DUT_D12 (in, see 10, 13), DUT_D13 (in, see 10, 13), DUT_D14 (in, see 10, 13), DUT_D15 (in, see 10, 13), DUT_D16/FCLK (in, see 10, 13), DUT_D17 (in, see 10, 13), DUT_DCLK (in, see 10, 13)

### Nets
1p8V_BUFVCC: C81.2 C82.2 C83.2 C84.2 R138.2 U22.7(VCC) U22.22(VCC) U22.35(VCC) U22.50(VCC)
GND: C81.1 C82.1 C83.1 C84.1 R180.1 U22.4(GND) U22.11(GND) U22.18(GND) U22.25(GND) U22.32(GND) U22.39(GND) U22.46(GND) U22.53(GND)
D0: R140.2 U22.2(1Y1) ; port D0
D1: R142.2 U22.3(1Y2) ; port D1
D2: R144.2 U22.5(1Y3) ; port D2
D3: R146.2 U22.6(1Y4) ; port D3
D4: R151.2 U22.8(1Y5) ; port D4
D5: R153.2 U22.9(1Y6) ; port D5
D6: R155.2 U22.10(1Y7) ; port D6
D7: R157.2 U22.12(1Y8) ; port D7
D8: R159.2 U22.13(1Y9) ; port D8
D9: R161.2 U22.14(1Y10) ; port D9
D10: R163.2 U22.15(2Y1) ; port D10
D11: R167.2 U22.17(2Y3) ; port D11
D12: R169.2 U22.19(2Y4) ; port D12
D13: R171.2 U22.20(2Y5) ; port D13
D14: R173.2 U22.21(2Y6) ; port D14
D15: R175.2 U22.23(2Y7) ; port D15
D16/FCLK: R177.2 U22.24(2Y8) ; port D16/FCLK
D17: R179.2 U22.26(2Y9) ; port D17
DCLK: R165.2 U22.16(2Y2) ; port DCLK
DUT_D0: R139.1 U22.55(1A1) ; port DUT_D0
DUT_D1: R141.1 U22.54(1A2) ; port DUT_D1
DUT_D2: R143.1 U22.52(1A3) ; port DUT_D2
DUT_D4: R150.1 U22.49(1A5) ; port DUT_D4
DUT_D5: R152.1 U22.48(1A6) ; port DUT_D5
DUT_D6: R154.1 U22.47(1A7) ; port DUT_D6
DUT_D7: R156.1 U22.45(1A8) ; port DUT_D7
DUT_D8: R158.1 U22.44(1A9) ; port DUT_D8
DUT_D9: R160.1 U22.43(1A10) ; port DUT_D9
DUT_D10: R162.1 U22.42(2A1) ; port DUT_D10
DUT_D11: R166.1 U22.40(2A3) ; port DUT_D11
DUT_D12: R168.1 U22.38(2A4) ; port DUT_D12
DUT_D13: R170.1 U22.37(2A5) ; port DUT_D13
DUT_D14: R172.1 U22.36(2A6) ; port DUT_D14
DUT_D15: R174.1 U22.34(2A7) ; port DUT_D15
DUT_D16/FCLK: R176.1 U22.33(2A8) ; port DUT_D16/FCLK
DUT_D17: R178.1 U22.31(2A9) ; port DUT_D17
DUT_DB1: R145.1 U22.51(1A4) ; port DUT_D3
DUT_DCLK: R164.1 U22.41(2A2) ; port DUT_DCLK
NetR138_1: R138.1 R180.2 U22.1(1~{OE1}) U22.28(2~{OE1}) U22.29(2~{OE2}) U22.30(2A10) U22.56(1~{OE2})
NetR139_2: R139.2 R140.1
NetR141_2: R141.2 R142.1
NetR143_2: R143.2 R144.1
NetR145_2: R145.2 R146.1
NetR150_2: R150.2 R151.1
NetR152_2: R152.2 R153.1
NetR154_2: R154.2 R155.1
NetR156_2: R156.2 R157.1
NetR158_2: R158.2 R159.1
NetR160_2: R160.2 R161.1
NetR162_2: R162.2 R163.1
NetR164_2: R164.2 R165.1
NetR166_2: R166.2 R167.1
NetR168_2: R168.2 R169.1
NetR170_2: R170.2 R171.1
NetR172_2: R172.2 R173.1
NetR174_2: R174.2 R175.1
NetR176_2: R176.2 R177.1
NetR178_2: R178.2 R179.1

Not connected (* = marked no-connect by the designer): U22 27(2Y10)*

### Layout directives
net class CMOS_BUF_Out: (no net found under the mark)

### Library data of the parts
C81-C84 = capcc09401: as C72 on sheet DUT IO
R138 R180 = RSMD020101206: RES SMD 12K OHM 5% 1/20W 0201; Manufacturer: Panasonic Electronic Components; CompType: Resistor SMD; Power (Watts): 0.05W, 1/20W; Temperature Coefficient: ±200ppm/°C
R139-R146 R150-R179 = RSMD020101699: as R73 on sheet ADC Inputs
U22 = SN74ALVCH16827DGG: 20-Bit Buffer/Driver With 3-State Outputs, DGG0056A, LARGE T&R; Manufacturer: Texas Instruments; CompType: Buffer

## Sheet Hardware & Mechanicals.SchDoc: Hardware & Mechanicals
size 431 x 279 mm; Date: Not shown in title block; ApprovedBy: Not shown in title block; CheckedBy: Not shown in title block; Author: Not shown in title block; CompanyName: Not shown in title block; Engineer: Not shown in title block; Organization: Not shown in title block; Address1: Not shown in title block; Address2: Not shown in title block; Address3: Not shown in title block; Address4: Not shown in title block; DocumentNumber: 4; Revision: Use project parameter SCH_Rev; SheetNumber: 14; SheetTotal: 14; PageSetup: Record=PageOptions¦CenterHorizontal=True¦CenterVertical=True¦PrintScale=1.00¦XCorrection=1.00¦YCorrection=1.00¦PrintKind=0¦BorderSize=5000000¦LeftOffset=0¦BottomOffset=0¦Orientation=2¦PaperLength=1000¦PaperWidth=1000¦Scale=100¦PaperSource=15¦PrintQuality=600¦MediaType=1¦DitherType=10¦PaperKind=Letter¦PrintScaleMode=1
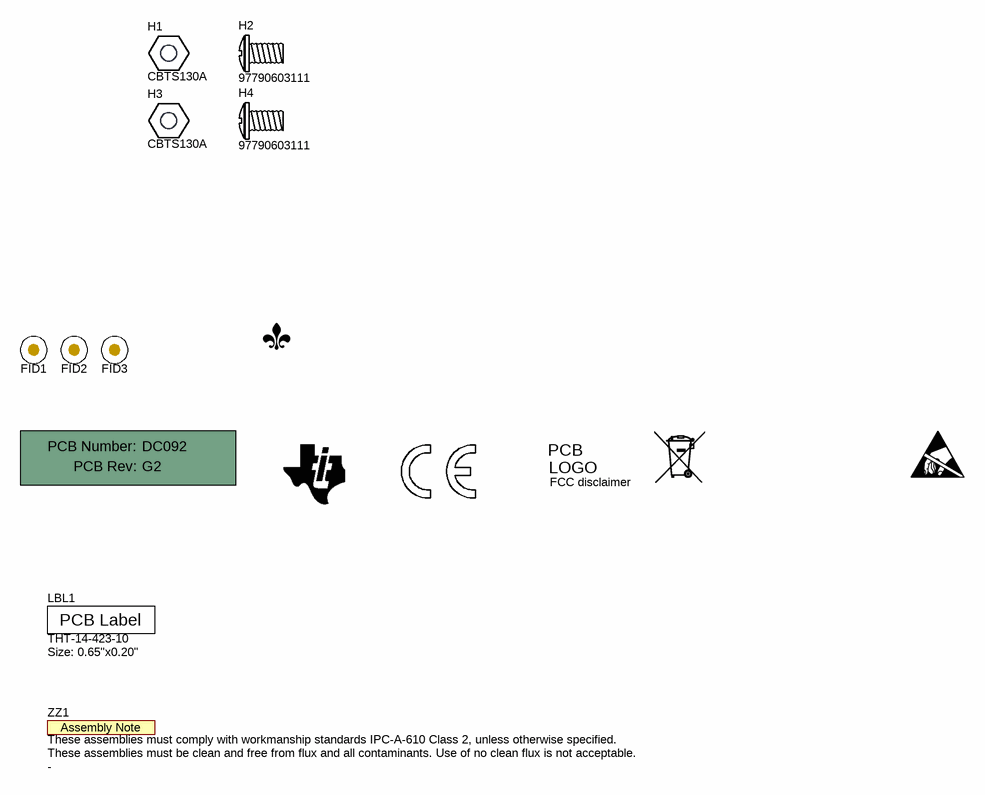
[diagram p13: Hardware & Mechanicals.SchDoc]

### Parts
!PCB1  (no value)  (mechanical)
FID1  Fiducial Mark  [Fiducial10-20]  (value not drawn)  (no BOM)
FID2  Fiducial Mark  [Fiducial10-20]  (value not drawn)  (no BOM)
FID3  Fiducial Mark  [Fiducial10-20]  (value not drawn)  (no BOM)
H1  CBTS130A  [cbts130a]
H2  97790603111  [97790603111]  (mechanical)
H3  CBTS130A  [cbts130a]
H4  97790603111  [97790603111]  (mechanical)
LBL1  THT-14-423-10  Text1: Size: 0.65"x0.20"  [Label_650x200]
Logo1  FDL Logo  [FDL_Small]  (value not drawn)  (no BOM)
Logo2  FCC disclaimer  [FCC_disclaimer]  (no BOM)
Logo3  ESD Overlay  [ESD_Overlay_Small]  (value not drawn)  (no BOM)
Logo4  WEEE  [WEEE_Minimum]  (value not drawn)  (no BOM)
LOGO5  CE Mark  [CE_Mark_5mm]  (value not drawn)  (no BOM)
Logo6  Texas Instruments  [TI_Stacked_Overlay_Small_Vertical]  (value not drawn)  (no BOM)
ZZ1  Text3: These assemblies must comply with workmanship standards IPC-A-610 Class 2, unless otherwise specified.  Text2: These assemblies must be clean and free from flux and all contaminants. Use of no clean flux is not acceptable.  [AssemblyNote]  (hidden comment: These assemblies are ESD sensitive, ESD precautions shall be observed.)  (no BOM)

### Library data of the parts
!PCB1 = cmp00109: Printed Circuit Board; CompType: PCB
FID1-FID3 = cmp00099: Fiducial; SymbolCreator: a0412235
H1 H3 = CBTS130A: Hex Standoff Threaded M3 Nylon 1.260" (32.00mm) Natural; Manufacturer: Essentra Components; UniqueID: CBTS010A
H2 H4 = 97790603111: M3 Pan Head Machine Screw Phillips Drive Nylon; Manufacturer: Murth Elektronik
LBL1 = cmp00106: Thermal Transfer Printable Labels, 0.650" W x 0.200" H - 10,000 per roll; Manufacturer: Brady; CompType: Label
Logo1 = cmp00105: FDL
Logo2 = cmp00102: FCC_disclaimer; CompType: Logo
Logo3 = cmp00317: PartNumber: ESD Logo; CompType: Logo
Logo4 = cmp00101: CompType: Logo
LOGO5 = cmp00103: CE_Mark; CompType: Logo
Logo6 = cmp00104: Texas Instrument Corporate Signature; PartNumber: TI Bug; CompType: Logo
ZZ1 = cmp00108: Assembly Notes

## Sheet Revision History.SchDoc: Rev History & Variants
size 431 x 279 mm; Date: Not shown in title block; ApprovedBy: Not shown in title block; CheckedBy: Not shown in title block; Author: Not shown in title block; CompanyName: Not shown in title block; Engineer: Not shown in title block; Organization: Not shown in title block; Address1: Not shown in title block; Address2: Not shown in title block; Address3: Not shown in title block; Address4: Not shown in title block; DocumentNumber: 5; Revision: Use project parameter SCH_Rev; SheetNumber: 15; SheetTotal: 15; PageSetup: Record=PageOptions¦CenterHorizontal=True¦CenterVertical=True¦PrintScale=1.00¦XCorrection=1.00¦YCorrection=1.00¦PrintKind=0¦BorderSize=5000000¦LeftOffset=0¦BottomOffset=0¦Orientation=2¦PaperLength=1000¦PaperWidth=1000¦Scale=100¦PaperSource=15¦PrintQuality=600¦MediaType=1¦DitherType=10¦PaperKind=Letter¦PrintScaleMode=1
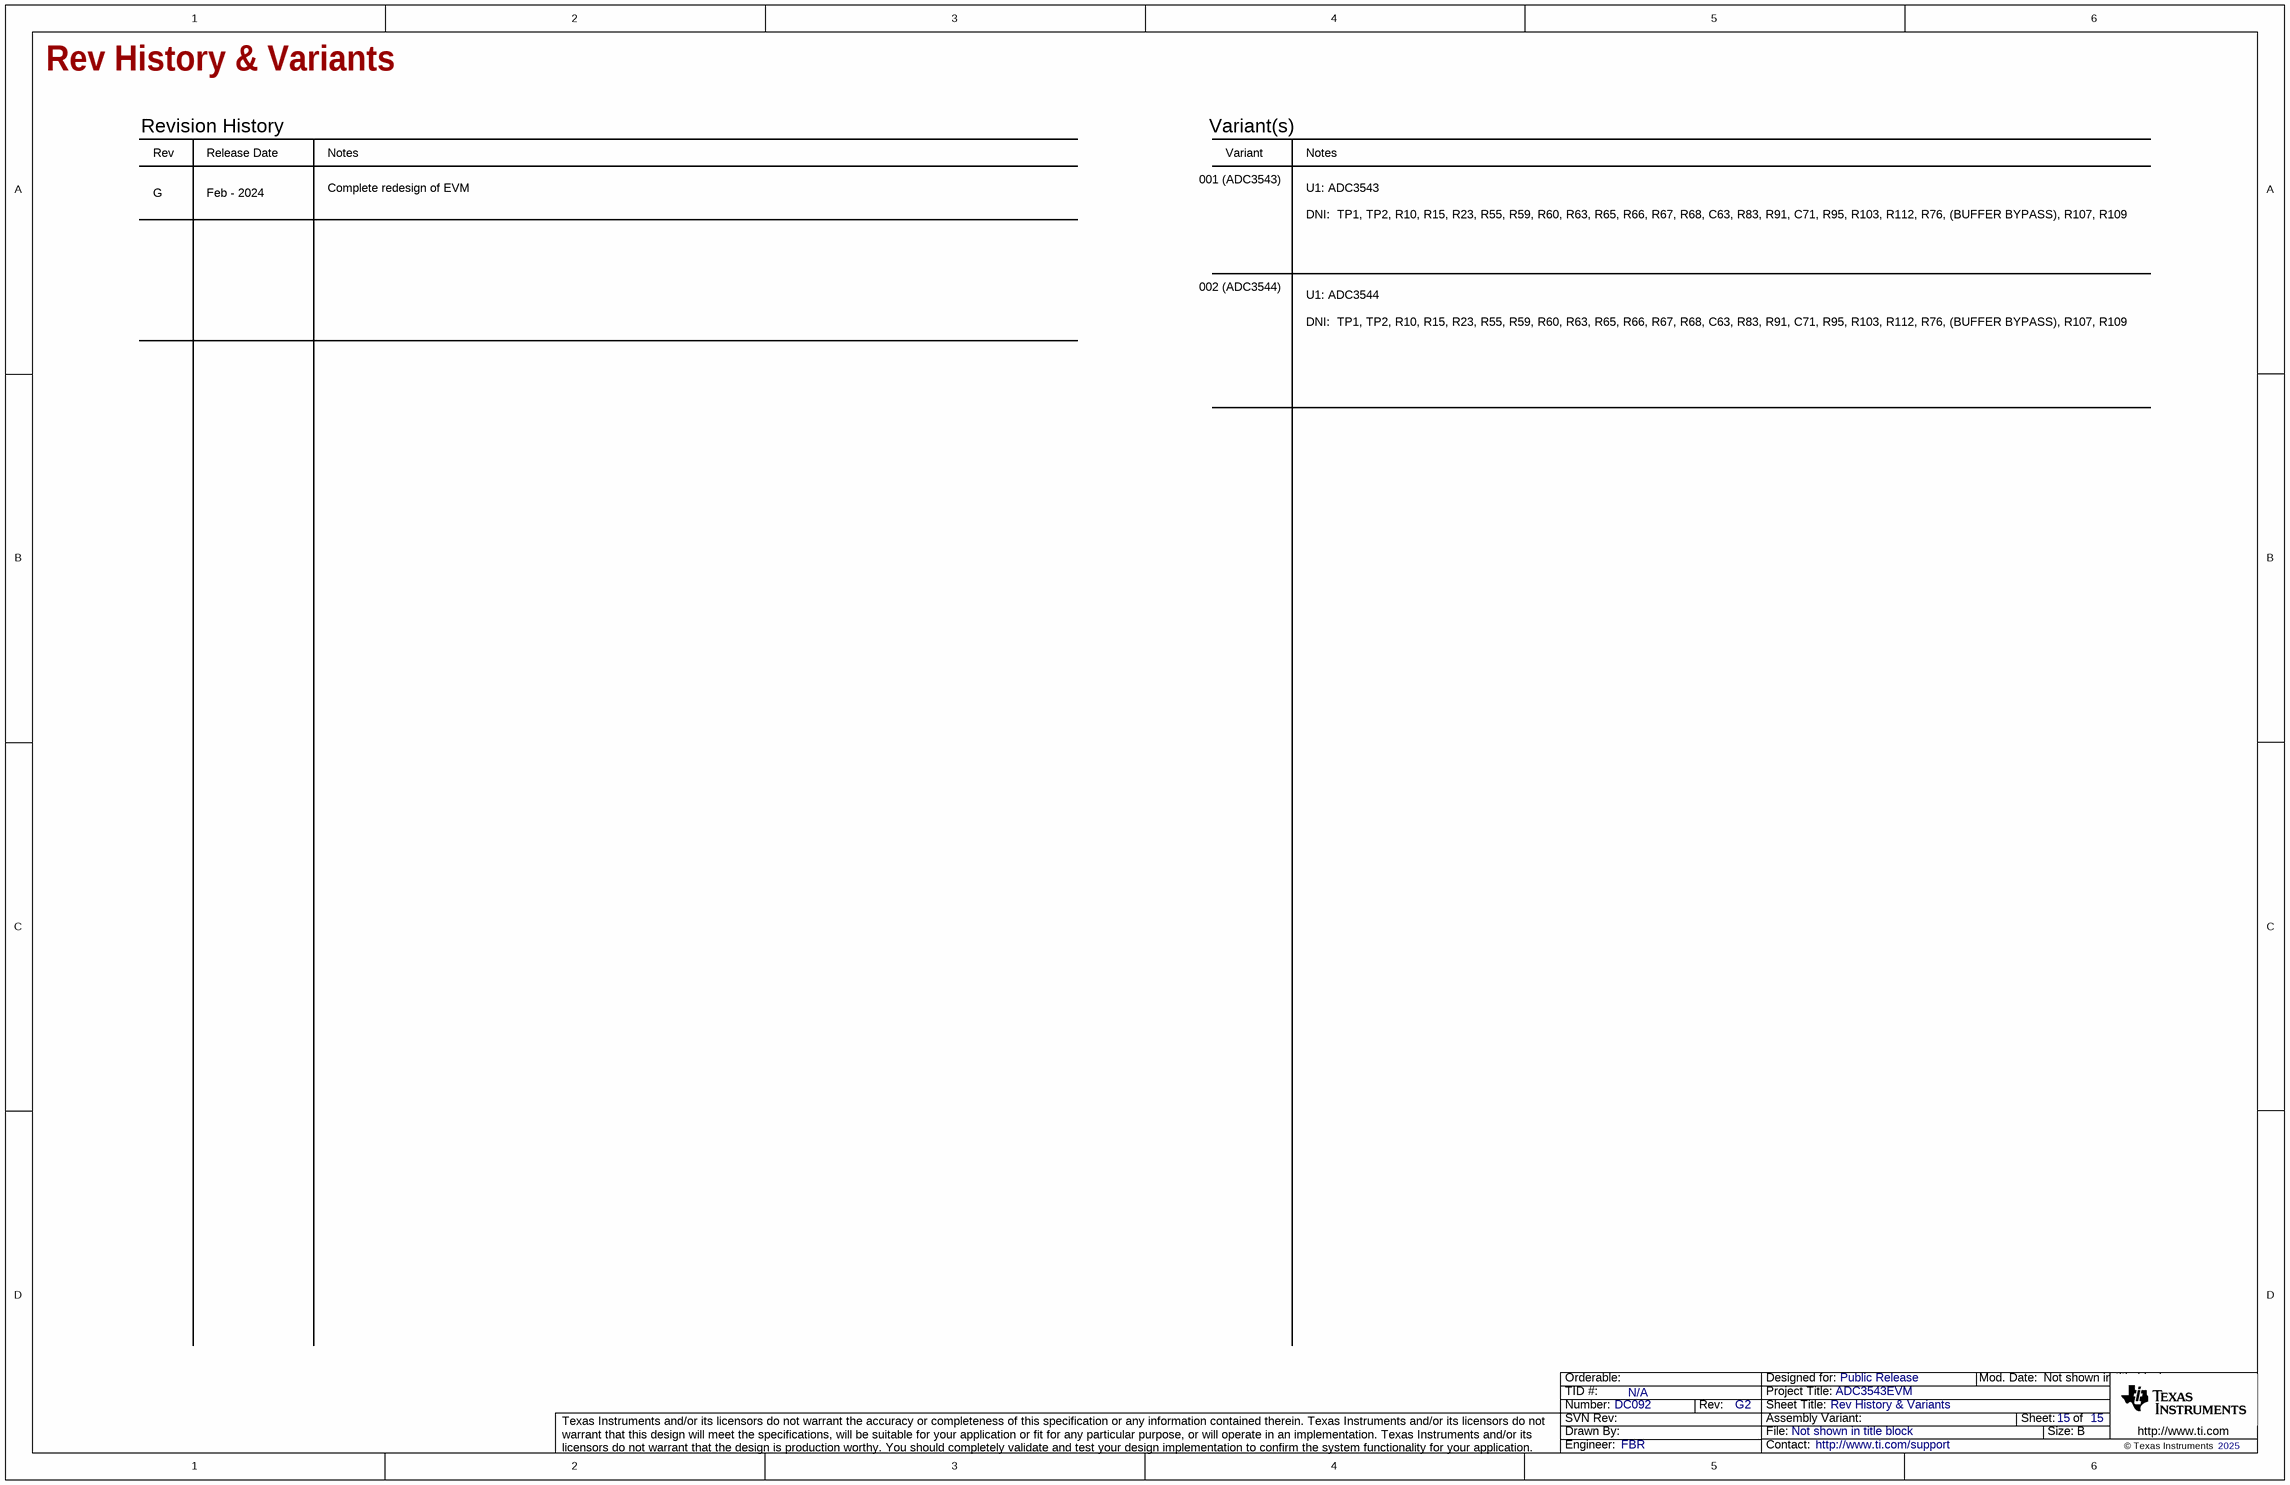
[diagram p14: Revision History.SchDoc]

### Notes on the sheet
- Rev
- Release Date
- Revision History
- Notes
- Variant
- Variant(s)
- G
- Feb - 2024
- Complete redesign of EVM
- 001 (ADC3543)
- 002 (ADC3544)
- U1: ADC3543
  DNI:  TP1, TP2, R10, R15, R23, R55, R59, R60, R63, R65, R66, R67, R68, C63, R83, R91, C71, R95, R103, R112, R76, (BUFFER BYPASS), R107, R109
- U1: ADC3544
  DNI:  TP1, TP2, R10, R15, R23, R55, R59, R60, R63, R65, R66, R67, R68, C63, R83, R91, C71, R95, R103, R112, R76, (BUFFER BYPASS), R107, R109

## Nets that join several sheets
1p8V_AVDD: Power LDO (C21.2 FB2.2 PP3.1), Power Sense ADC (U8.8), DUT IO (7 pins)
1p8V_BUFVCC: Power LDO (C29.2 FC1.3), Ouptut Buffer (9 pins)
1p8V_IOVDD: Power LDO (C27.2 FB3.2 PP4.1), Power Sense ADC (U8.4), DUT IO (C69.2 U17.31)
1p8V_LVLSHIFT: Power LDO (7 pins), Comms LVL Shift and MUX (9 pins), CLK and DCLKIN (R69.2), DUT IO (7 pins)
2p3V: Power DC-DC (5 pins), Power LDO (10 pins)
3p3V_Utility: 12V Input, Efuse and 3p3V Utility (6 pins), Power DC-DC (R9.2), Power LDO (6 pins), Power Sense ADC (6 pins), USB Control FTDI (24 pins), Comms LVL Shift and MUX (13 pins), CLK and DCLKIN (C56.2 R72.2 U16.10), DUT IO (C77.2 R121.2 U20.4)
12V: 12V Input, Efuse and 3p3V Utility (10 pins), Power DC-DC (C9.2 C10.2 R10.2 U3.18), Power LDO (D4.1 D5.1)
12V_FMC: 12V Input, Efuse and 3p3V Utility (SW1.3), FMC+ Sections A-E (J1.C35 J1.C37)
GND: 12V Input, Efuse and 3p3V Utility (16 pins), Power DC-DC (24 pins), Power LDO (26 pins), Power Sense ADC (7 pins), USB Control FTDI (32 pins), Comms LVL Shift and MUX (20 pins), CLK and DCLKIN (22 pins), ADC Inputs (12 pins), DUT IO (32 pins), FMC+ Sections A-E (96 pins), FMC+ Sections F-H, J, K (72 pins), Ouptut Buffer (13 pins)
VADJ: FMC+ Sections A-E (J1.E39), FMC+ Sections F-H, J, K (J1.F40 J1.G39 J1.H40)
VCM: ADC Inputs (C61.2 R78.1 R79.2), DUT IO (C70.2 C71.2 TP3.1 U17.9)
3p3VU_PG: 12V Input, Efuse and 3p3V Utility (R5.1 U2.7), Power DC-DC (R10.1 U3.24)
AIN_N: ADC Inputs (R84.2), DUT IO (U17.14)
AIN_P: ADC Inputs (R76.2), DUT IO (U17.13)
CLK_N: CLK and DCLKIN (C55.2 R65.1), DUT IO (U17.7)
CLK_P: CLK and DCLKIN (C49.2 R65.2), DUT IO (U17.6)
D0: FMC+ Sections F-H, J, K (J1.H7), Ouptut Buffer (R140.2 U22.2)
D1: FMC+ Sections F-H, J, K (J1.G9), Ouptut Buffer (R142.2 U22.3)
D2: FMC+ Sections F-H, J, K (J1.H10), Ouptut Buffer (R144.2 U22.5)
D3: FMC+ Sections A-E (J1.C10), Ouptut Buffer (R146.2 U22.6)
D4: FMC+ Sections A-E (J1.D11), Ouptut Buffer (R151.2 U22.8)
D5: FMC+ Sections F-H, J, K (J1.G12), Ouptut Buffer (R153.2 U22.9)
D6: FMC+ Sections F-H, J, K (J1.H13), Ouptut Buffer (R155.2 U22.10)
D7: FMC+ Sections A-E (J1.D14), Ouptut Buffer (R157.2 U22.12)
D8: FMC+ Sections A-E (J1.C14), Ouptut Buffer (R159.2 U22.13)
D9: FMC+ Sections F-H, J, K (J1.H16), Ouptut Buffer (R161.2 U22.14)
D10: FMC+ Sections F-H, J, K (J1.G15), Ouptut Buffer (R163.2 U22.15)
D11: FMC+ Sections F-H, J, K (J1.H19), Ouptut Buffer (R167.2 U22.17)
D12: FMC+ Sections F-H, J, K (J1.G18), Ouptut Buffer (R169.2 U22.19)
D13: FMC+ Sections A-E (J1.D17), Ouptut Buffer (R171.2 U22.20)
D14: FMC+ Sections A-E (J1.D20), Ouptut Buffer (R173.2 U22.21)
D15: FMC+ Sections A-E (J1.C18), Ouptut Buffer (R175.2 U22.23)
D16/FCLK: FMC+ Sections A-E (J1.D8), Ouptut Buffer (R177.2 U22.24)
D17: FMC+ Sections A-E (J1.C22), Ouptut Buffer (R179.2 U22.26)
DC-DC_PG: Power DC-DC (R9.1 U3.19), Power LDO (R22.2)
DCLK: FMC+ Sections F-H, J, K (J1.G6), Ouptut Buffer (R165.2 U22.16)
DCLKIN: CLK and DCLKIN (U16.8), DUT IO (R117.1)
DUT_D0: DUT IO (R88.2), Ouptut Buffer (R139.1 U22.55)
DUT_D1: DUT IO (R90.2), Ouptut Buffer (R141.1 U22.54)
DUT_D2: DUT IO (R91.2), Ouptut Buffer (R143.1 U22.52)
DUT_D4: DUT IO (R93.2), Ouptut Buffer (R150.1 U22.49)
DUT_D5: DUT IO (R94.2), Ouptut Buffer (R152.1 U22.48)
DUT_D6: DUT IO (R95.2), Ouptut Buffer (R154.1 U22.47)
DUT_D7: DUT IO (R97.2), Ouptut Buffer (R156.1 U22.45)
DUT_D8: DUT IO (R98.2), Ouptut Buffer (R158.1 U22.44)
DUT_D9: DUT IO (R99.2), Ouptut Buffer (R160.1 U22.43)
DUT_D10: DUT IO (R100.2), Ouptut Buffer (R162.1 U22.42)
DUT_D11: DUT IO (R101.2), Ouptut Buffer (R166.1 U22.40)
DUT_D12: DUT IO (R102.2), Ouptut Buffer (R168.1 U22.38)
DUT_D13: DUT IO (R103.2), Ouptut Buffer (R170.1 U22.37)
DUT_D14: DUT IO (R104.2), Ouptut Buffer (R172.1 U22.36)
DUT_D15: DUT IO (R105.2), Ouptut Buffer (R174.1 U22.34)
DUT_D16/FCLK: DUT IO (R106.2), Ouptut Buffer (R176.1 U22.33)
DUT_D17: DUT IO (R107.2), Ouptut Buffer (R178.1 U22.31)
DUT_DB1: DUT IO (R113.1), Ouptut Buffer (R145.1 U22.51)
DUT_DCLK: DUT IO (R87.2), Ouptut Buffer (R164.1 U22.41)
FMC_~{CS}_DUT_LVLS: Comms LVL Shift and MUX (R59.1 U14.4), FMC+ Sections F-H, J, K (R133.1)
FMC_I2C_SCL: Comms LVL Shift and MUX (U12.4), FMC+ Sections A-E (R130.1)
FMC_I2C_SDA: Comms LVL Shift and MUX (U12.2), FMC+ Sections A-E (R131.1)
FMC_SCLK_DUT_LVLS: Comms LVL Shift and MUX (R58.1 U14.1), FMC+ Sections F-H, J, K (R134.1)
FMC_SDI_DUT: Comms LVL Shift and MUX (R147.2 U23.1), FMC+ Sections F-H, J, K (R136.1)
FMC_SDO_DUT_LVLS: Comms LVL Shift and MUX (5 pins), FMC+ Sections F-H, J, K (R135.1)
FPGA_DCLKIN: CLK and DCLKIN (U16.3), FMC+ Sections F-H, J, K (J1.H4)
FTDI_CSb_SHIFT: USB Control FTDI (U10.17), Comms LVL Shift and MUX (R52.1 U13.4)
FTDI_I2C_SCL: USB Control FTDI (R34.2 U9.3), Comms LVL Shift and MUX (U12.7)
FTDI_SCLK_SHIFT: USB Control FTDI (R35.2), Comms LVL Shift and MUX (R51.1 U13.3)
FTDI_SDI_SHIFT: USB Control FTDI (U10.19), Comms LVL Shift and MUX (R53.1 U13.6)
FTDI_SDO_SHIFT: USB Control FTDI (U10.18), Comms LVL Shift and MUX (U13.5)
IOVDD_PG: Power LDO (Q3.1 R23.1 U7.4), DUT IO (U19.1)
ISENSE_AVDD: Power LDO (U4.4), Power Sense ADC (U8.9)
ISENSE_IOVDD: Power LDO (U6.4), Power Sense ADC (U8.5)
PDN/SYNC: DUT IO (J10.3), FMC+ Sections F-H, J, K (R132.1)
PG-M2C: FMC+ Sections A-E (R128.1), FMC+ Sections F-H, J, K (J1.F1)
SCL_I2C: Power Sense ADC (U8.14), Comms LVL Shift and MUX (PP6.1 U12.6), FMC+ Sections A-E (U21.6)
SCLK_DUT: Comms LVL Shift and MUX (PP7.1 U14.2), DUT IO (R115.1)
SDA_I2C: Power Sense ADC (U8.13), Comms LVL Shift and MUX (PP5.1 U12.10), FMC+ Sections A-E (U21.5)
SDIO_DUT: Comms LVL Shift and MUX (PP9.1 U14.7), DUT IO (R116.1)
SEN_DUT: Comms LVL Shift and MUX (PP8.1 U14.5), DUT IO (R119.1)
USB_I2C_SDAr: USB Control FTDI (R37.2 R39.2 U10.28), Comms LVL Shift and MUX (U12.9)

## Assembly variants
001 (ADC3543): not fitted C63 C84 FID1 FID2 FID3 R10 R15 R23 R57 R60 R61 R63 R65 R66 R76 R83 R91 R107 R110 R112 R113 TP1 TP2 U22; alternate parts U1 -> ADC3663IRSB
002 (ADC3544): not fitted C63 C84 FID1 FID2 FID3 R10 R15 R23 R57 R60 R61 R63 R65 R66 R76 R83 R91 R108 R110 R112 R113 TP1 TP2 U22; alternate parts U1 -> ADC3544IRSB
